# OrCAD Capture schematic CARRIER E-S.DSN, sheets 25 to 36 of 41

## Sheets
25 B1B1: size A4; block Alimentacion/Alimentacion Digital
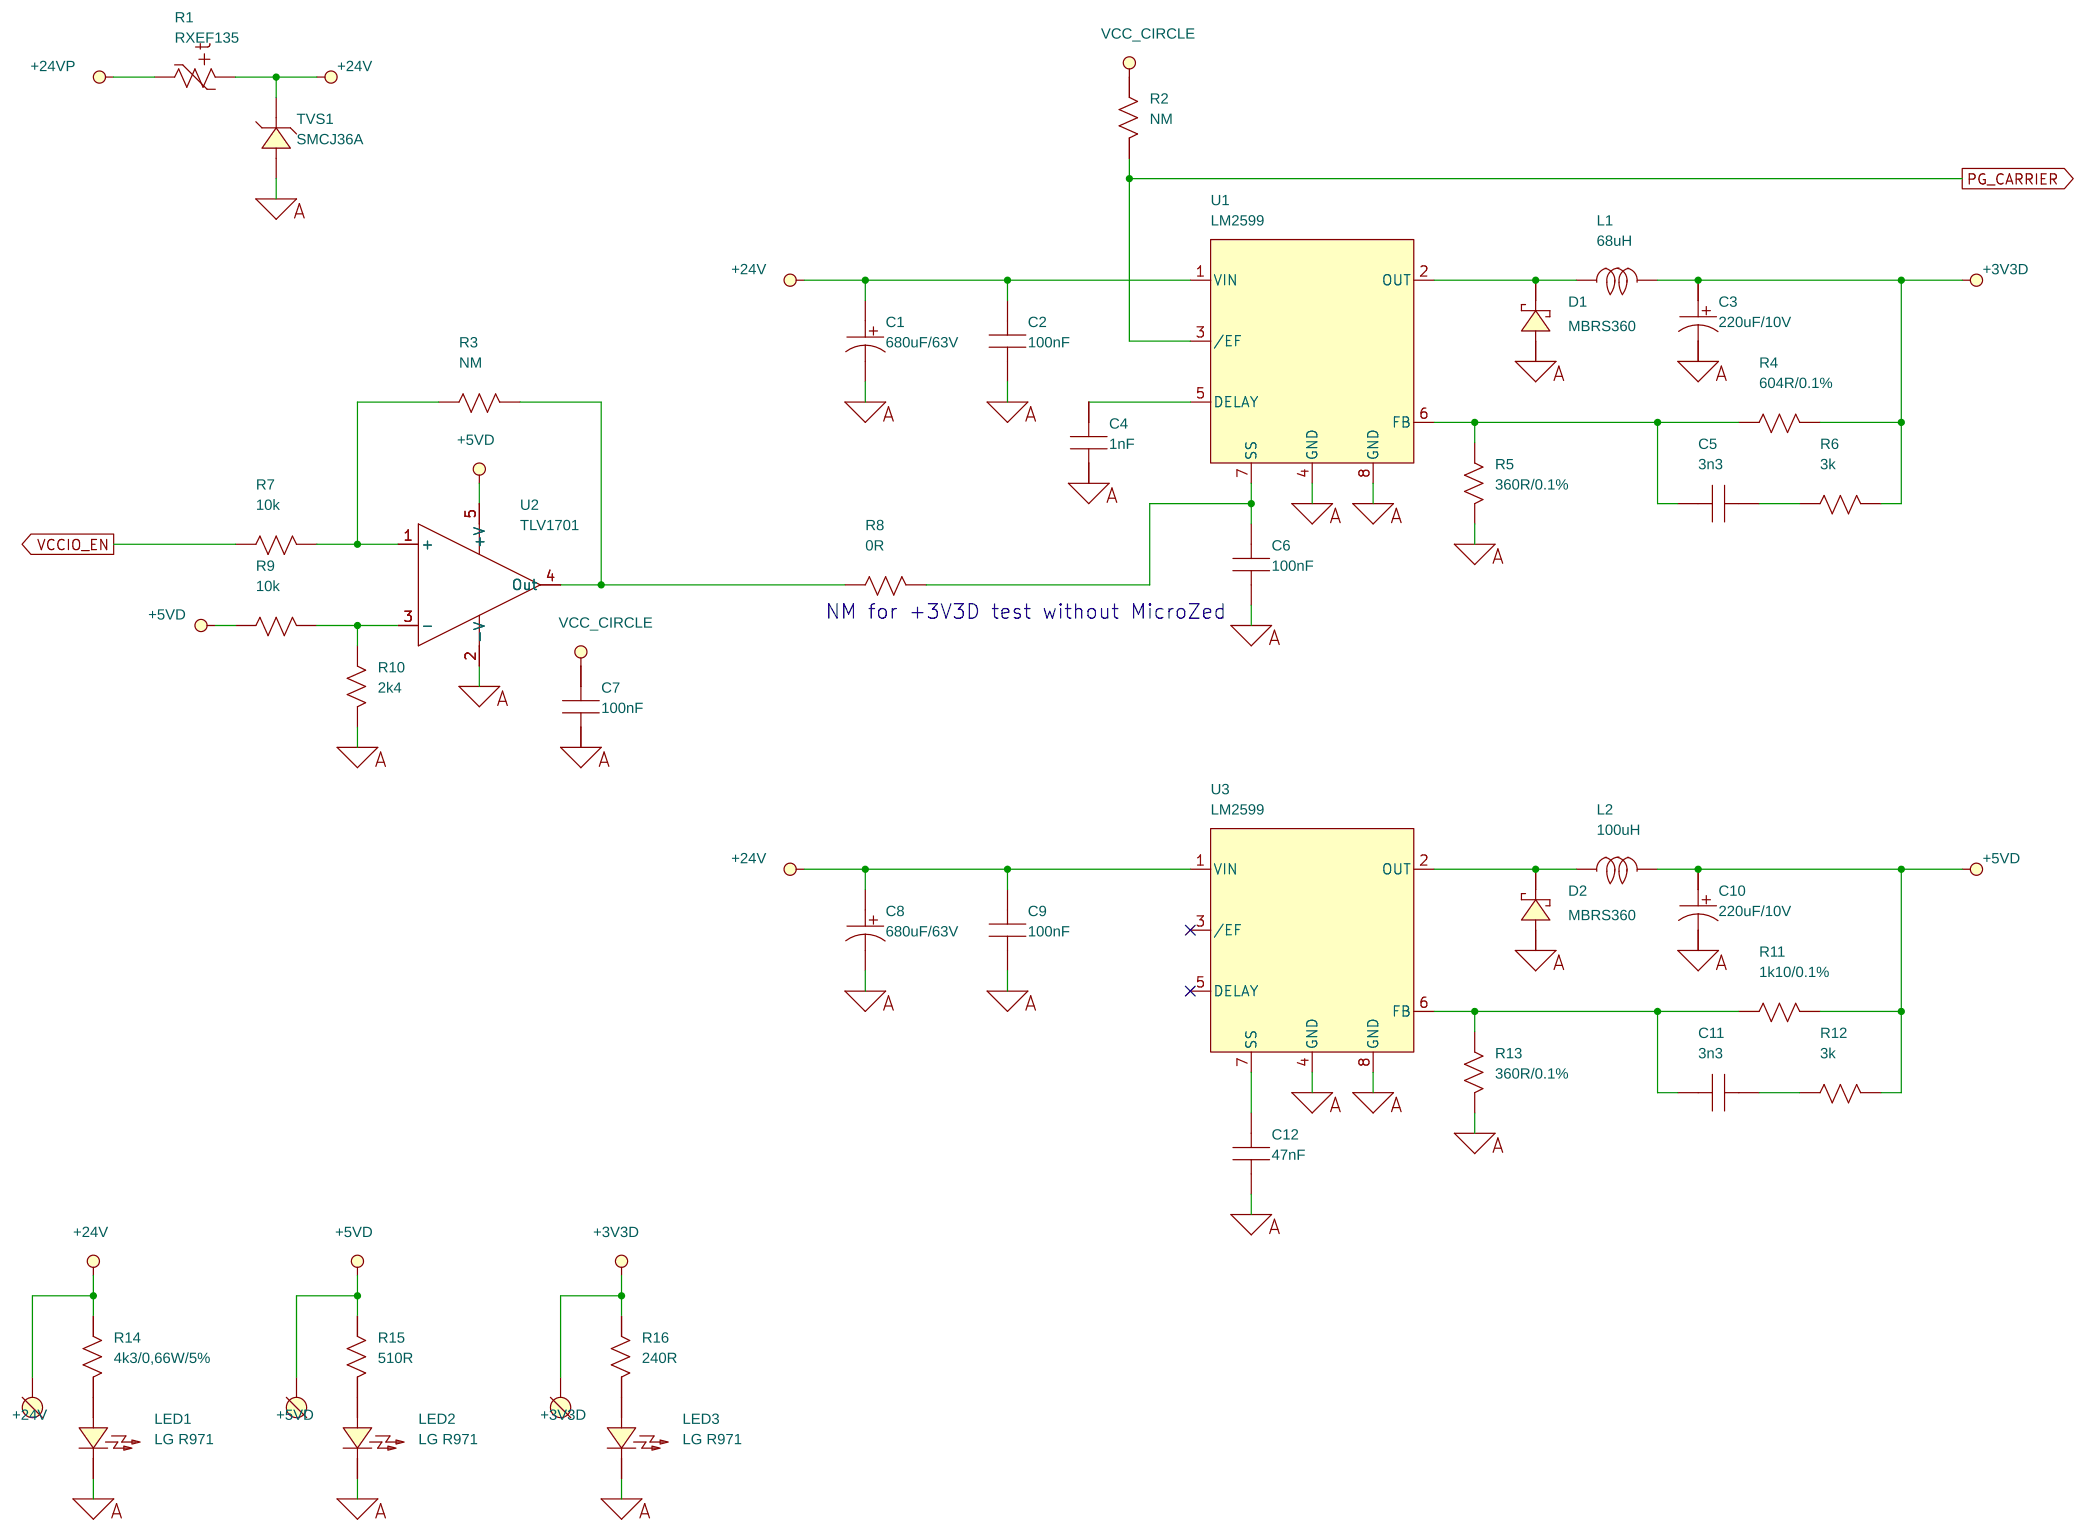
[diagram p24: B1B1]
26 B2: size A4; block IF MicroZed
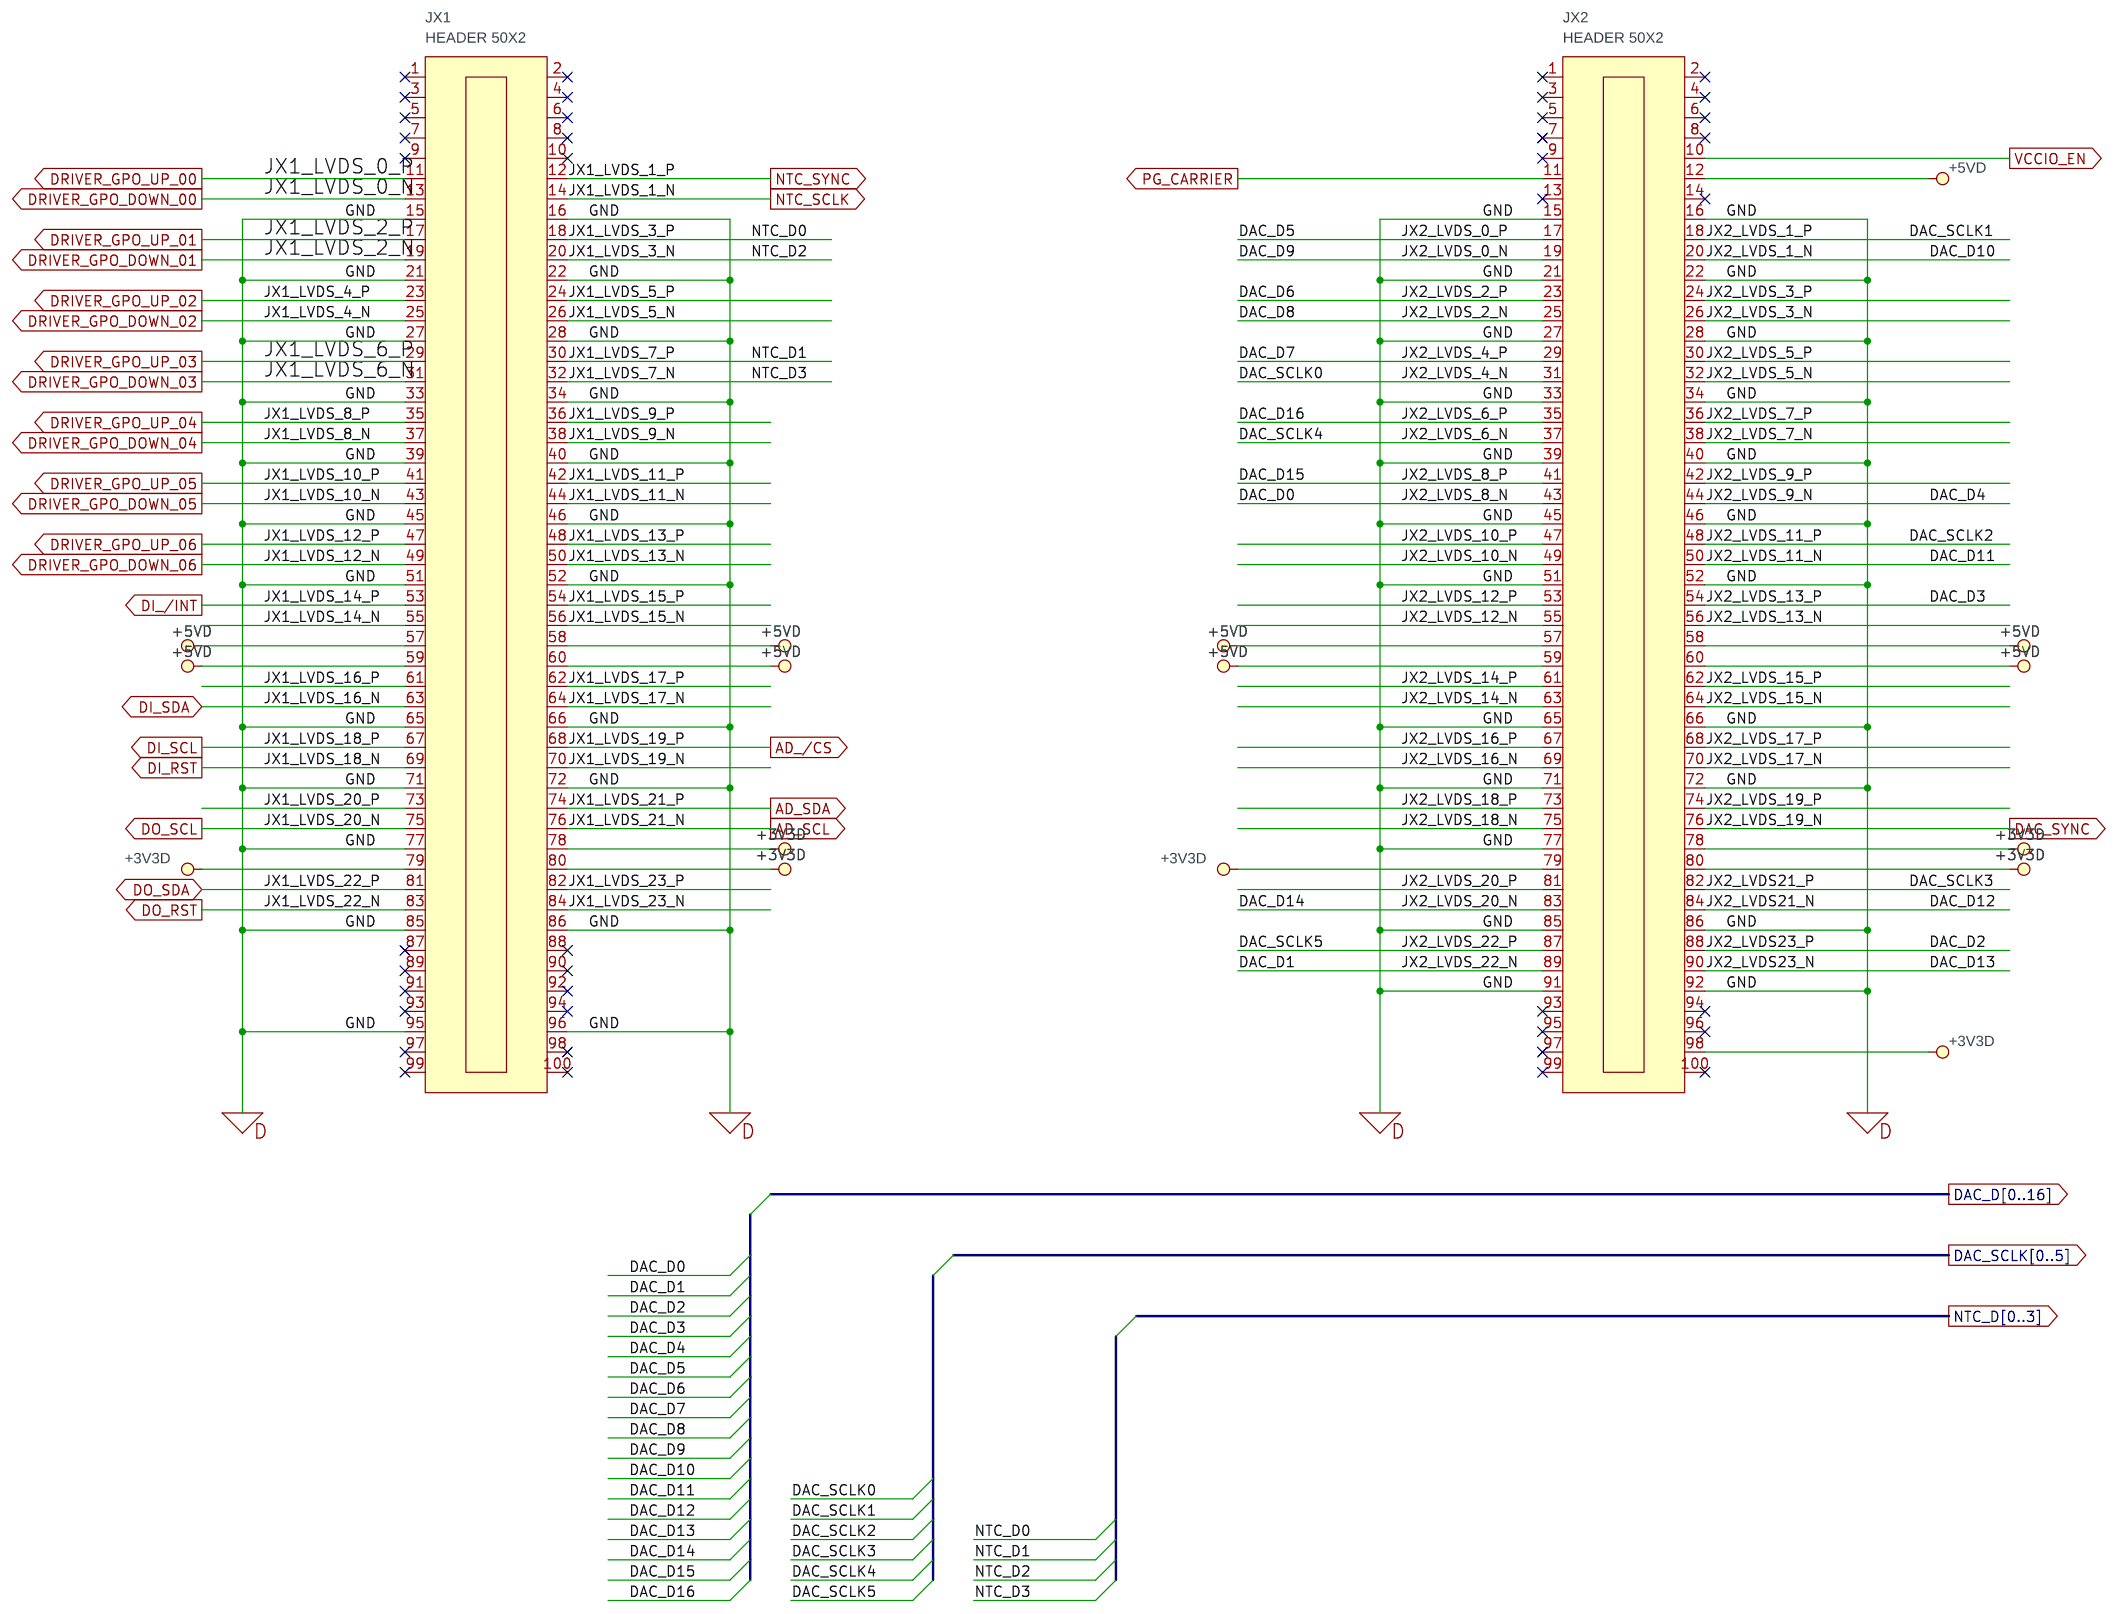
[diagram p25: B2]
27 B3B3
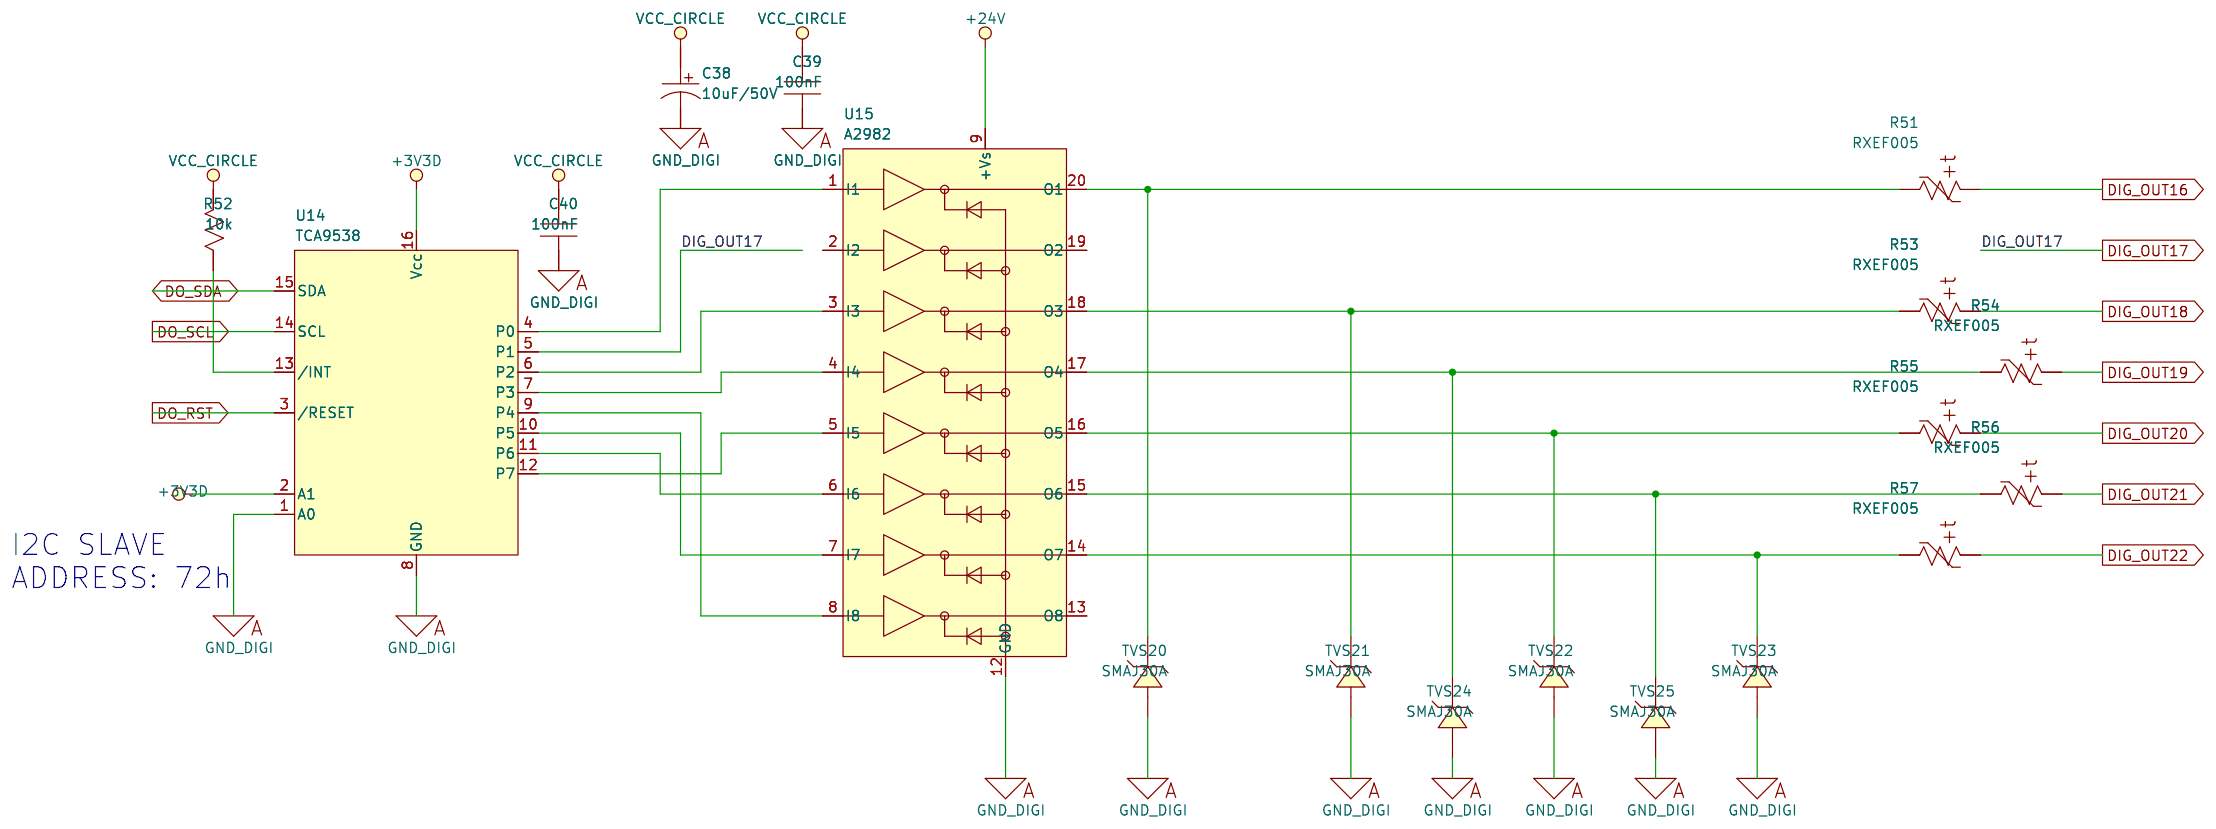
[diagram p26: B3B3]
28 B3B1
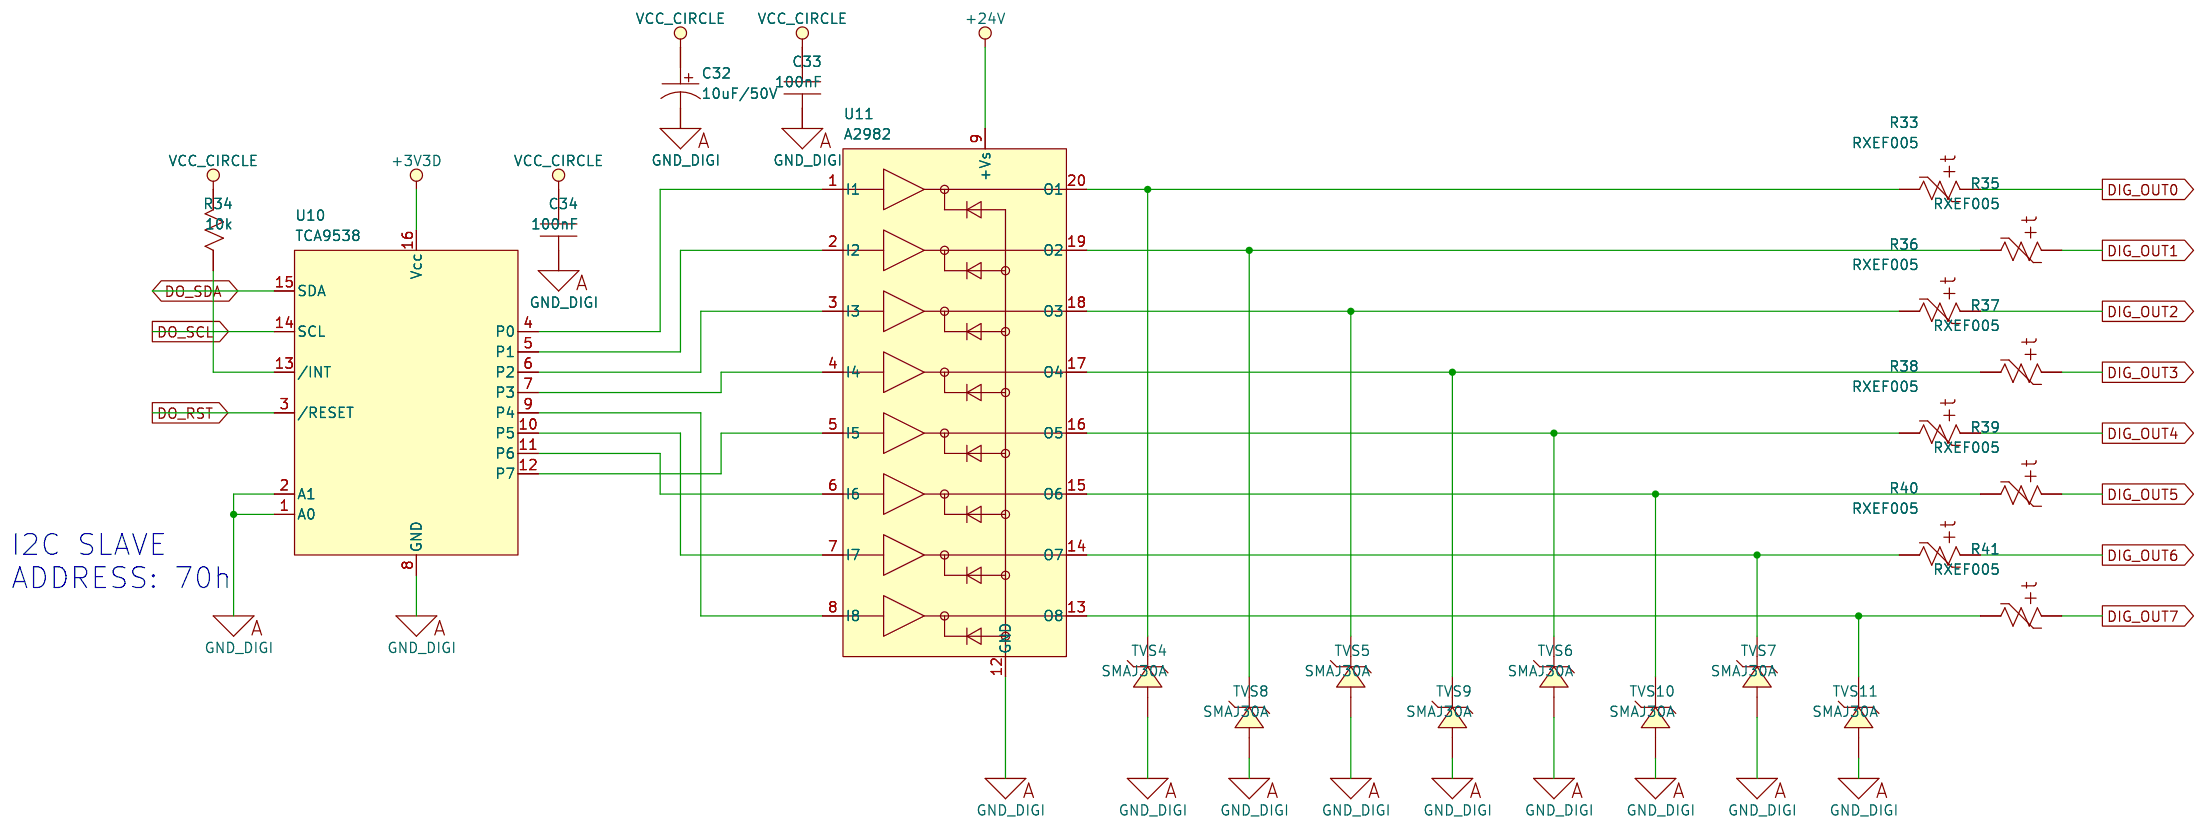
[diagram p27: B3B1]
29 B3B4
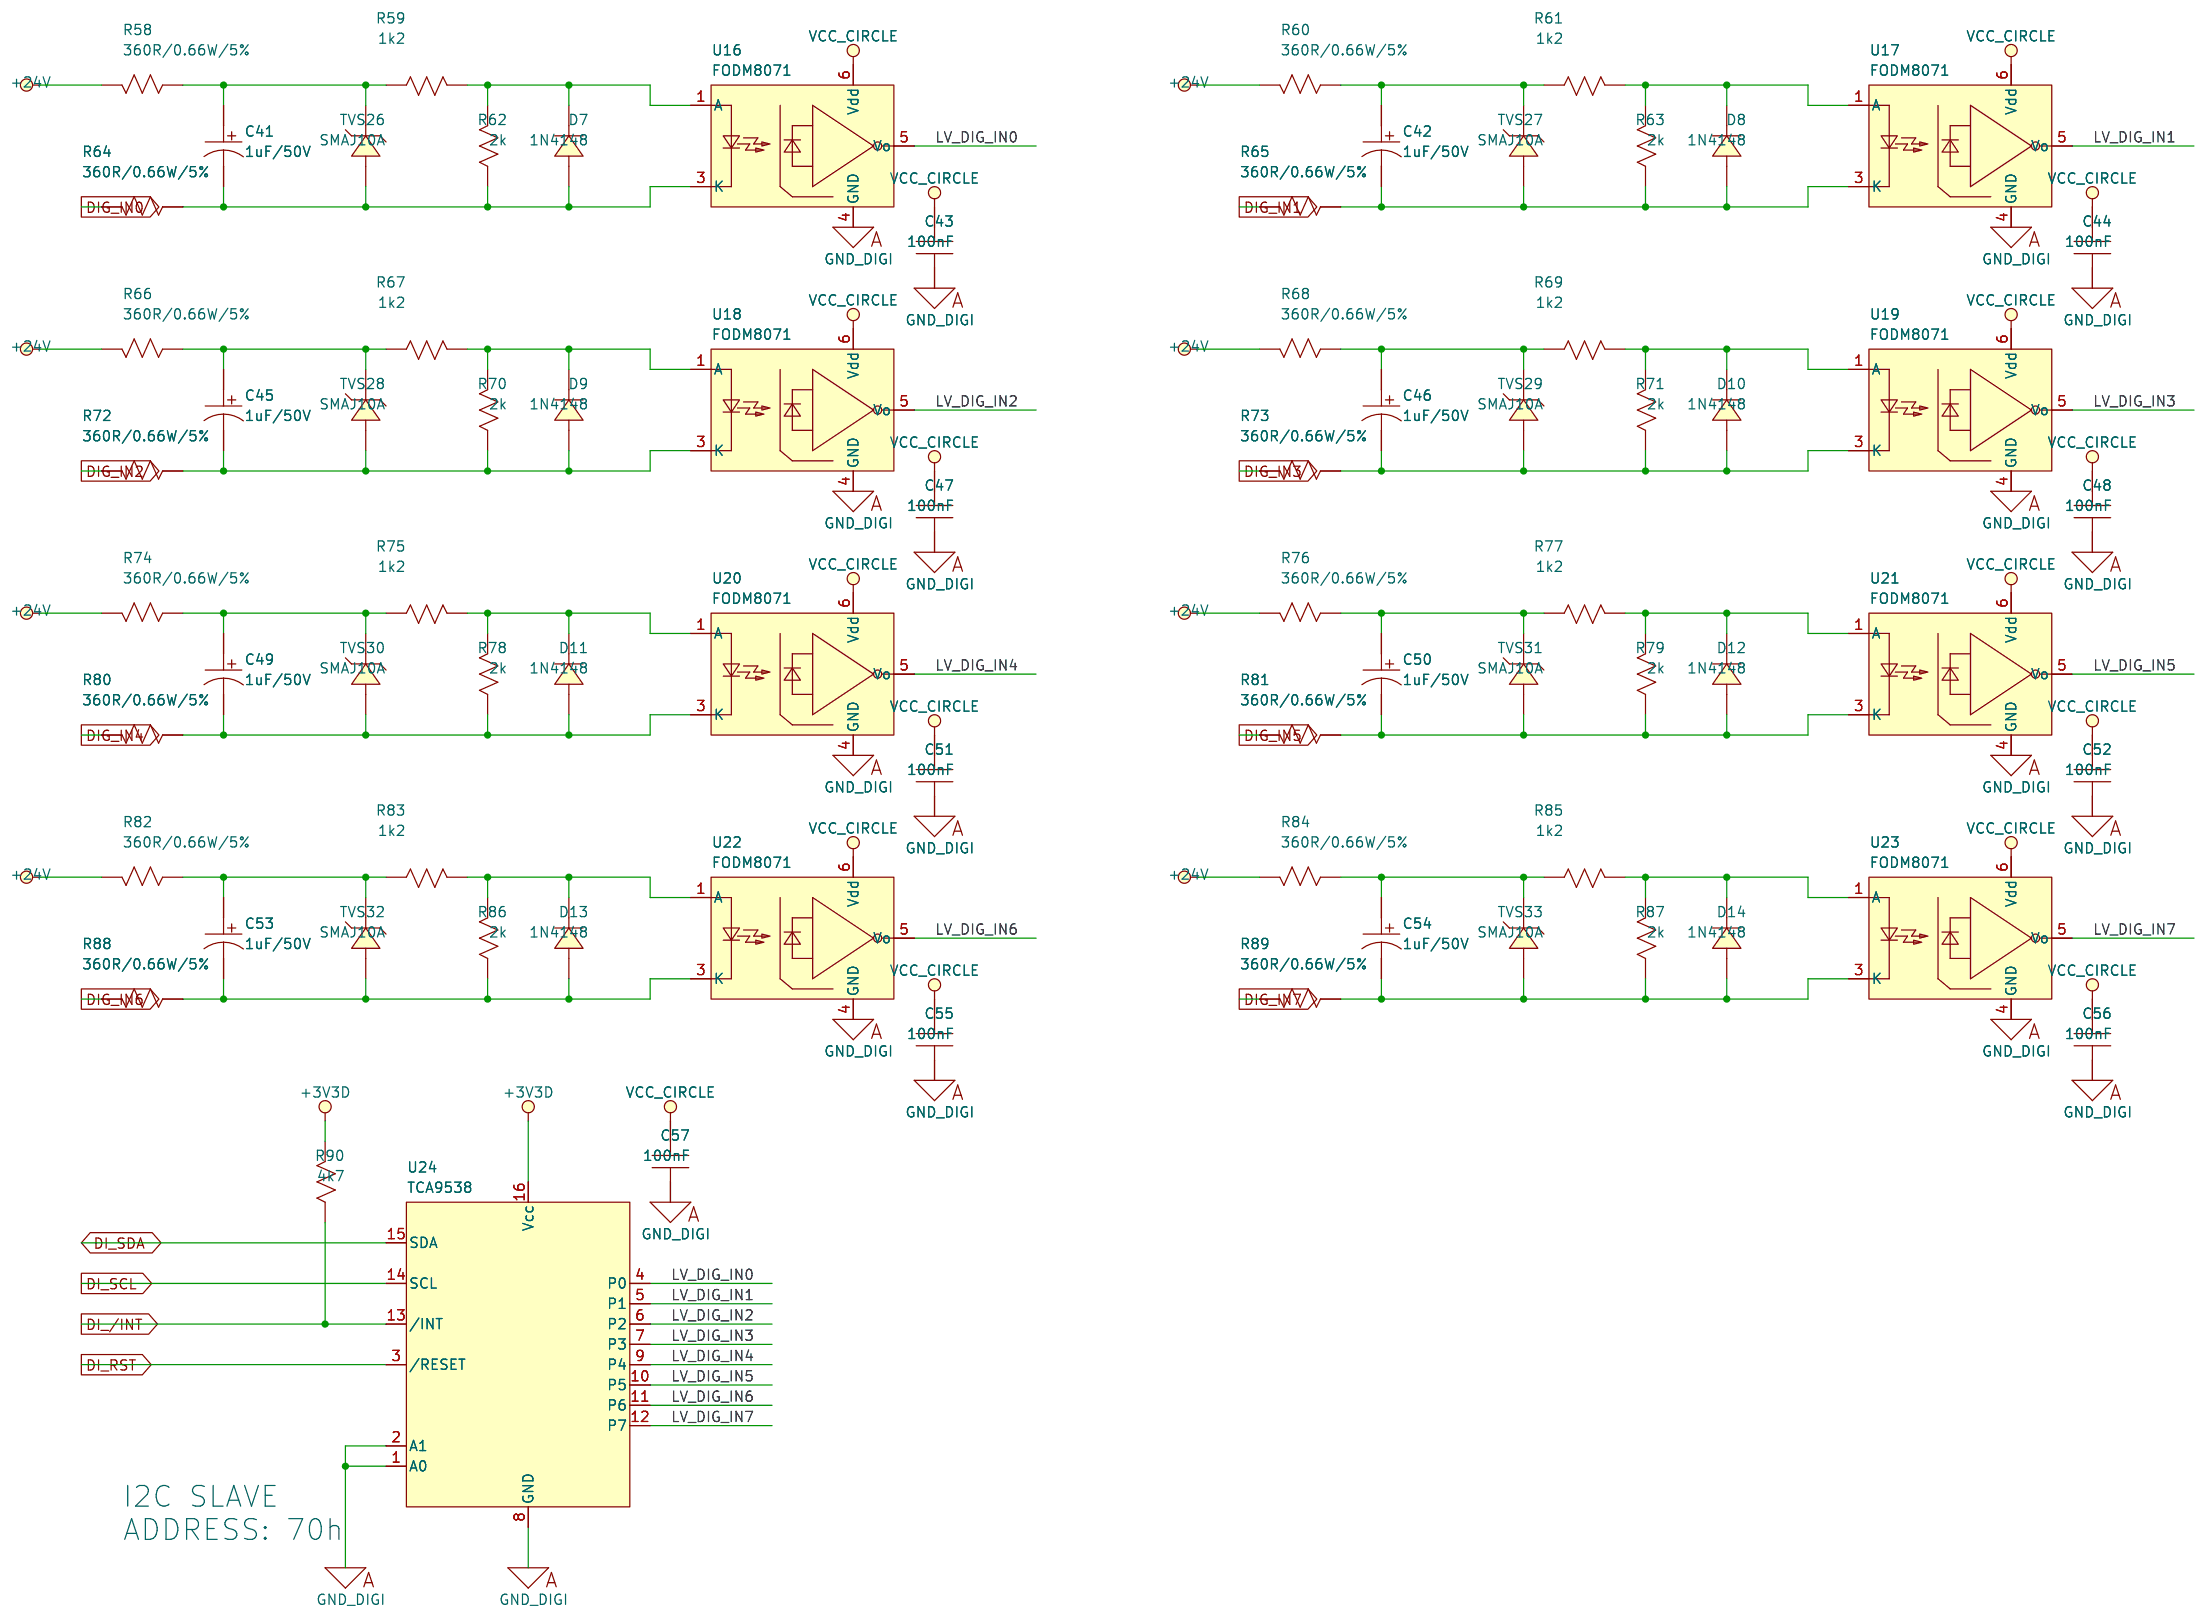
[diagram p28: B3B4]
30 B3B2
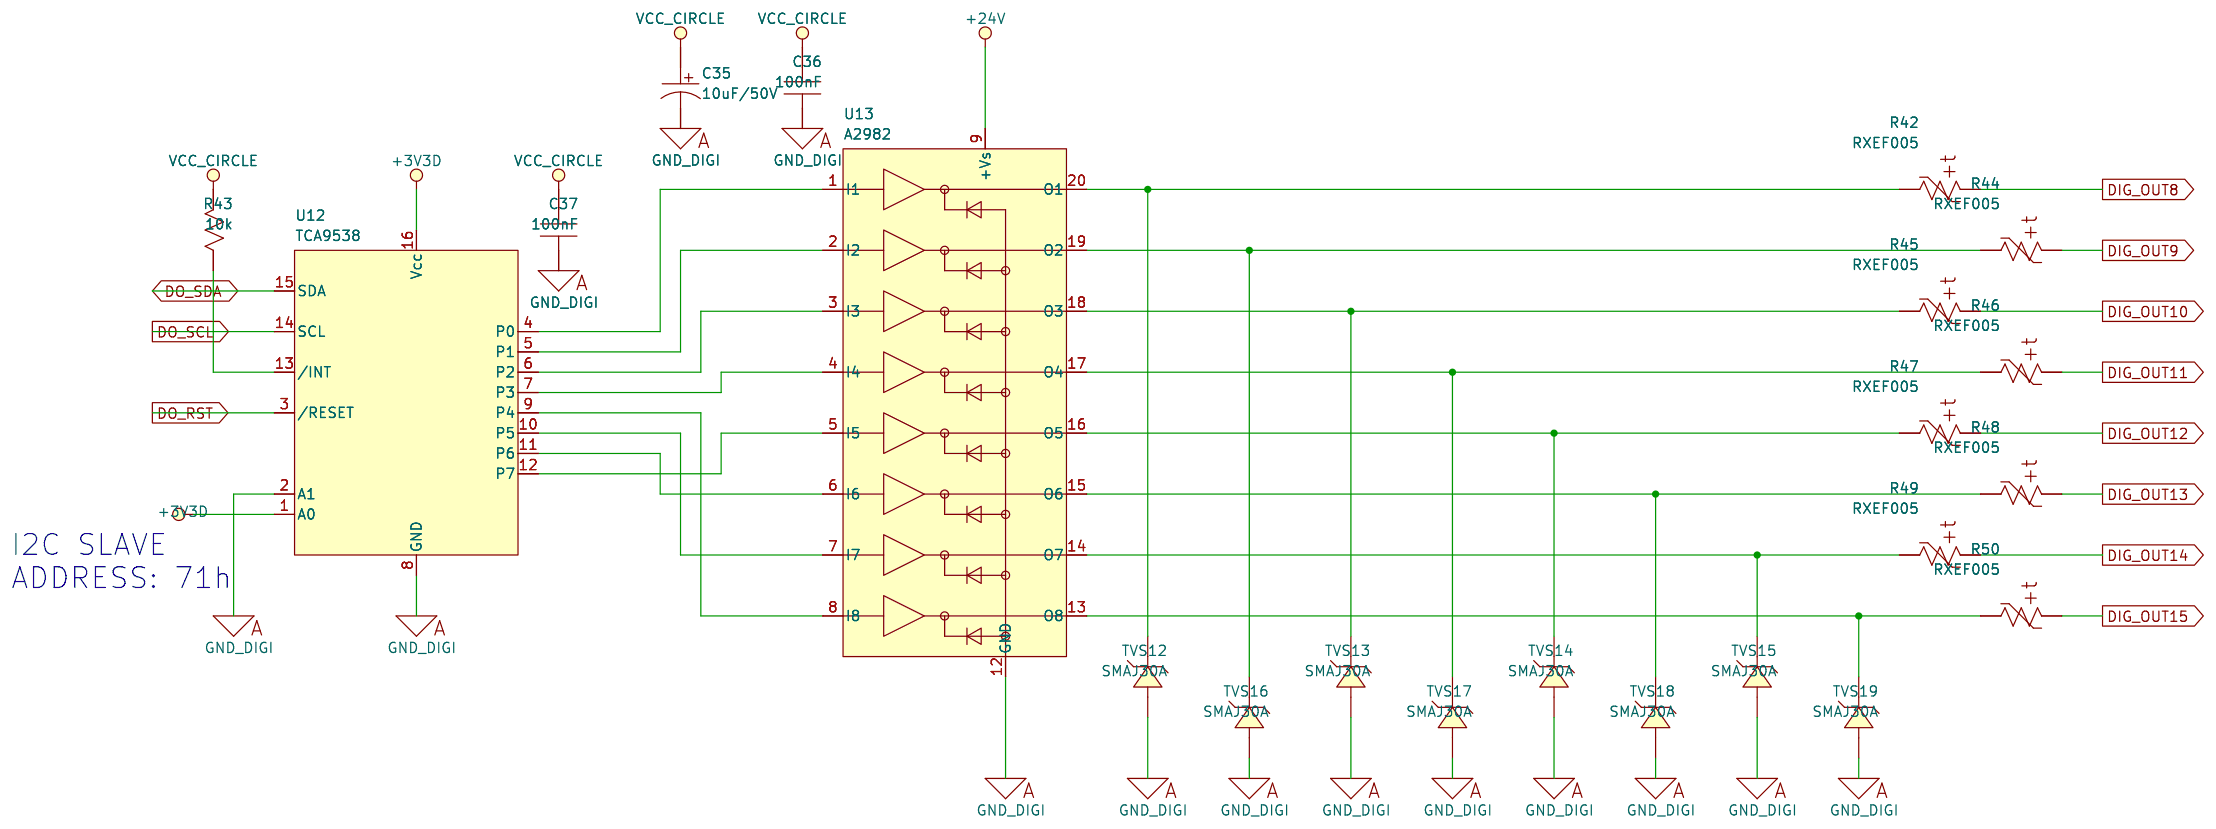
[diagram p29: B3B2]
31 B5: size A4; block Drivers IGBT
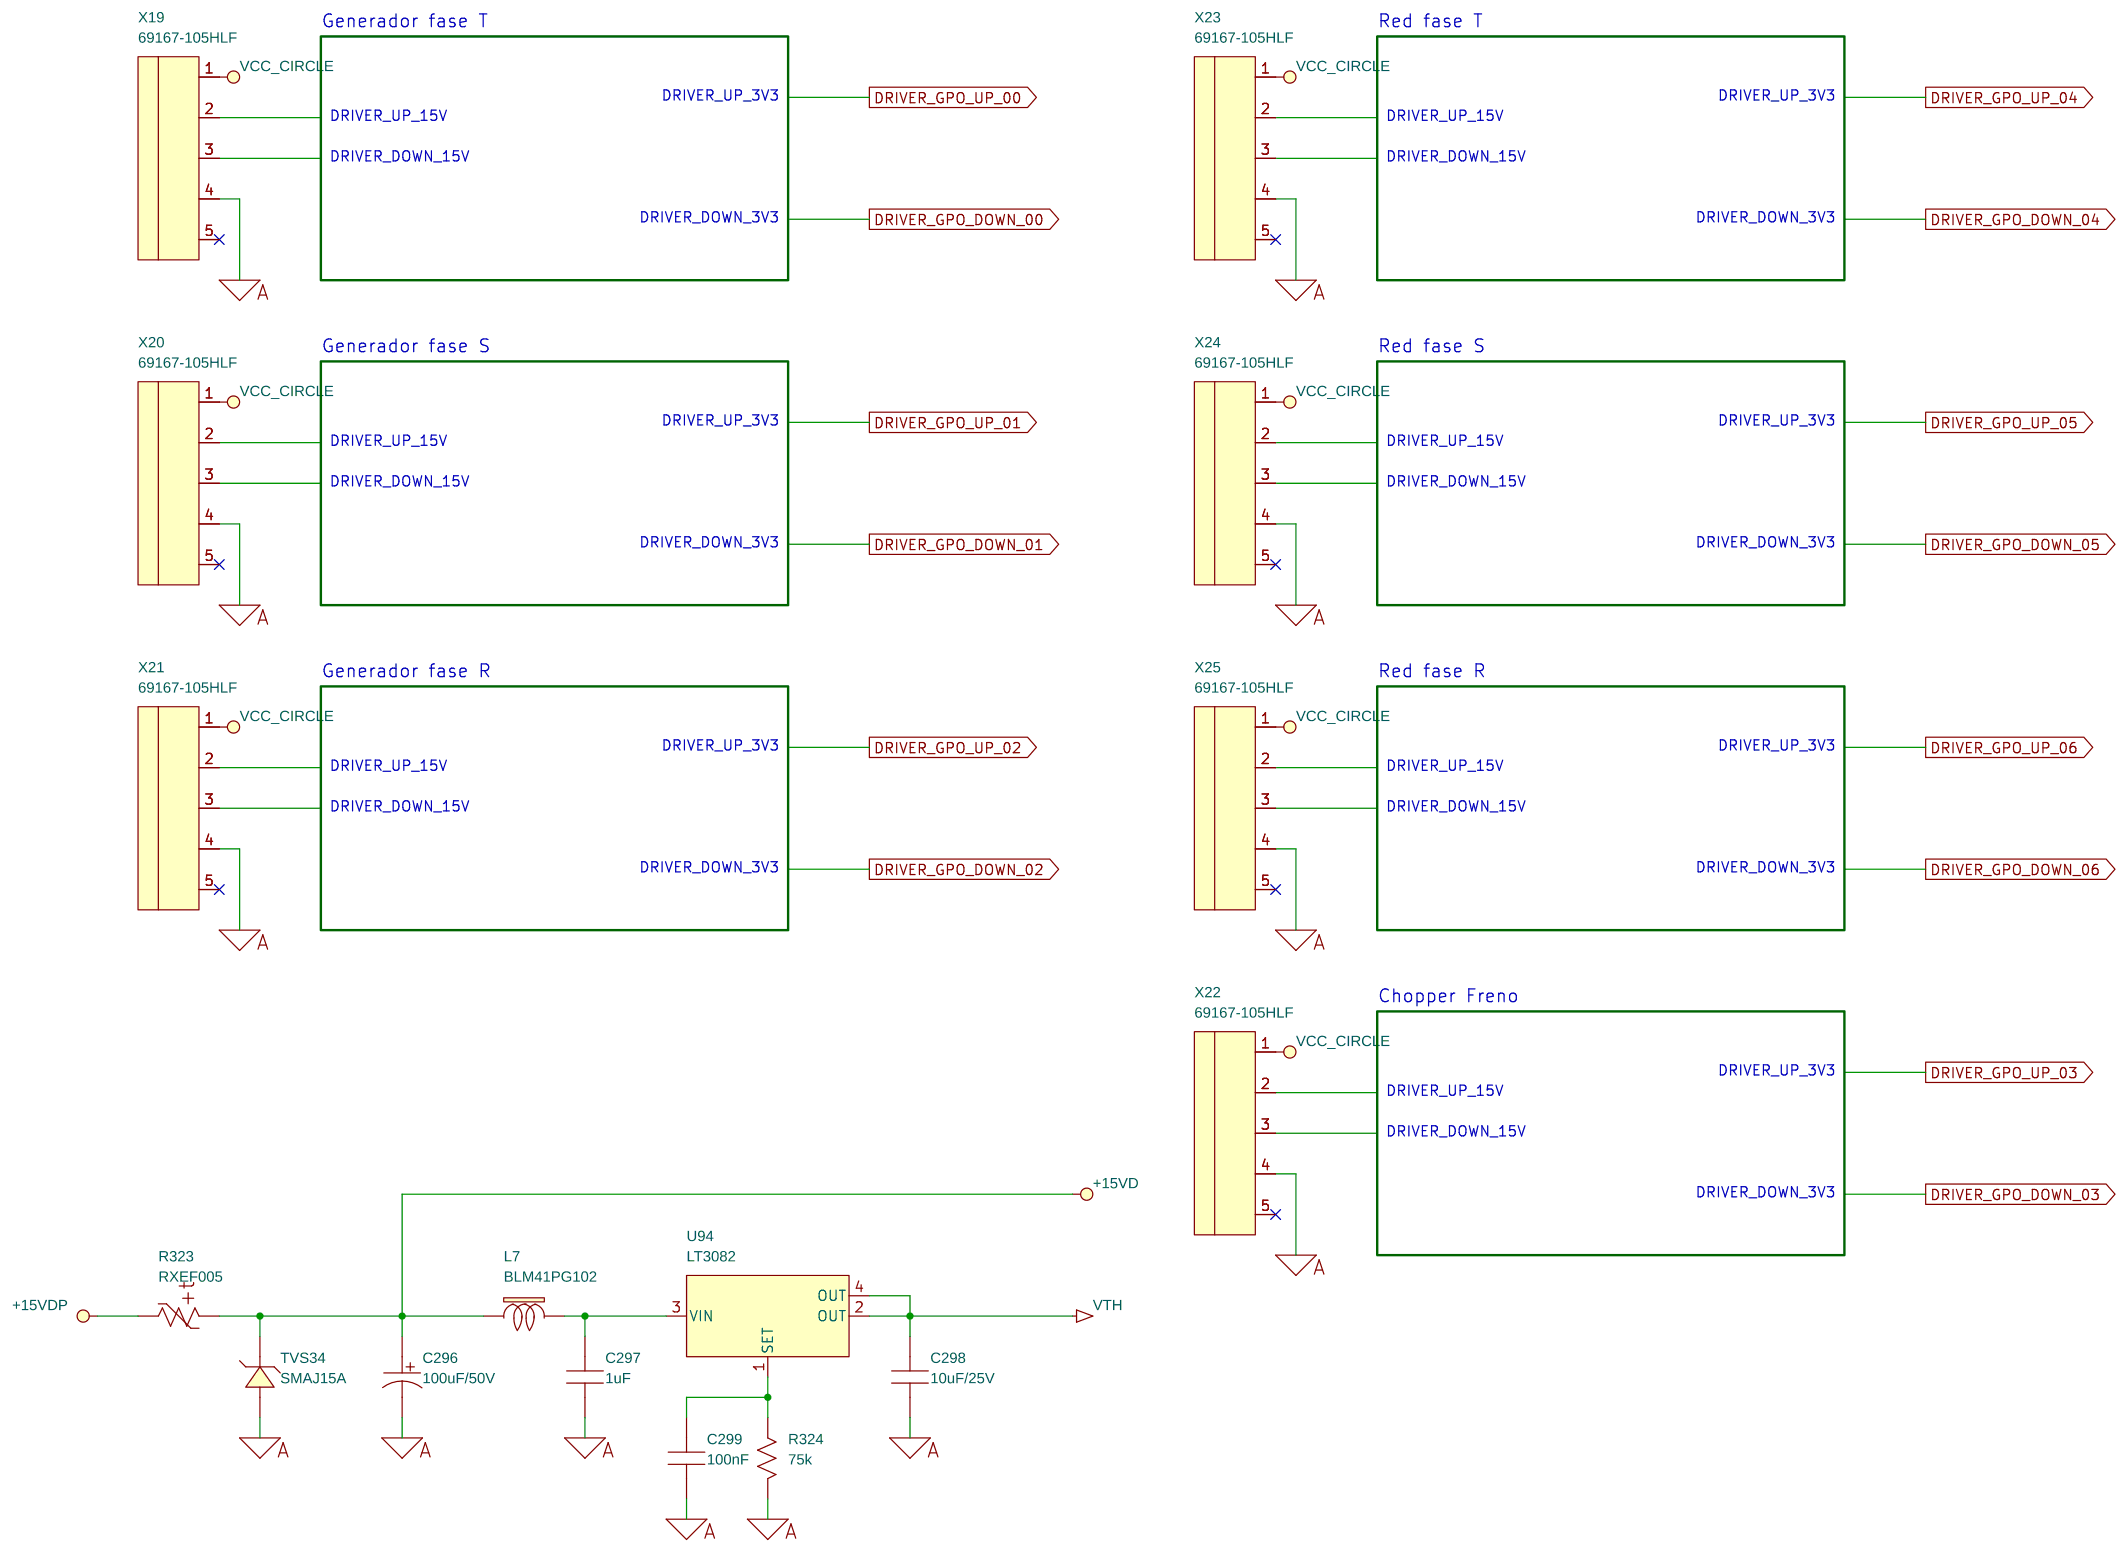
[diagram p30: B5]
32 B5B5: size A4; block Drivers IGBT/Red fase T
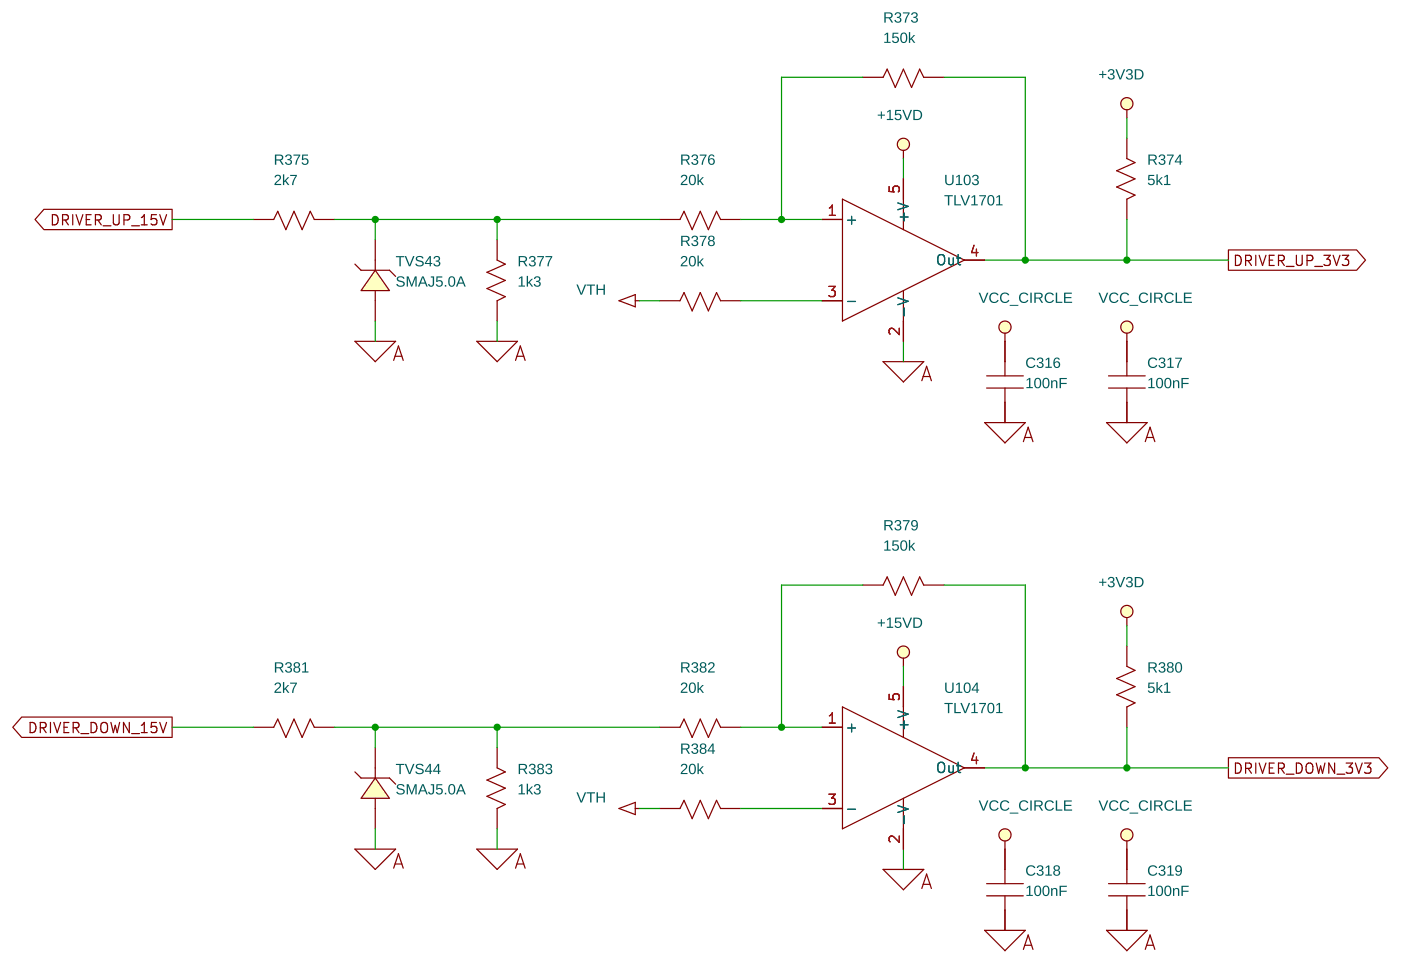
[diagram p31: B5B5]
33 B5B2: size A4; block Drivers IGBT/Generador fase S
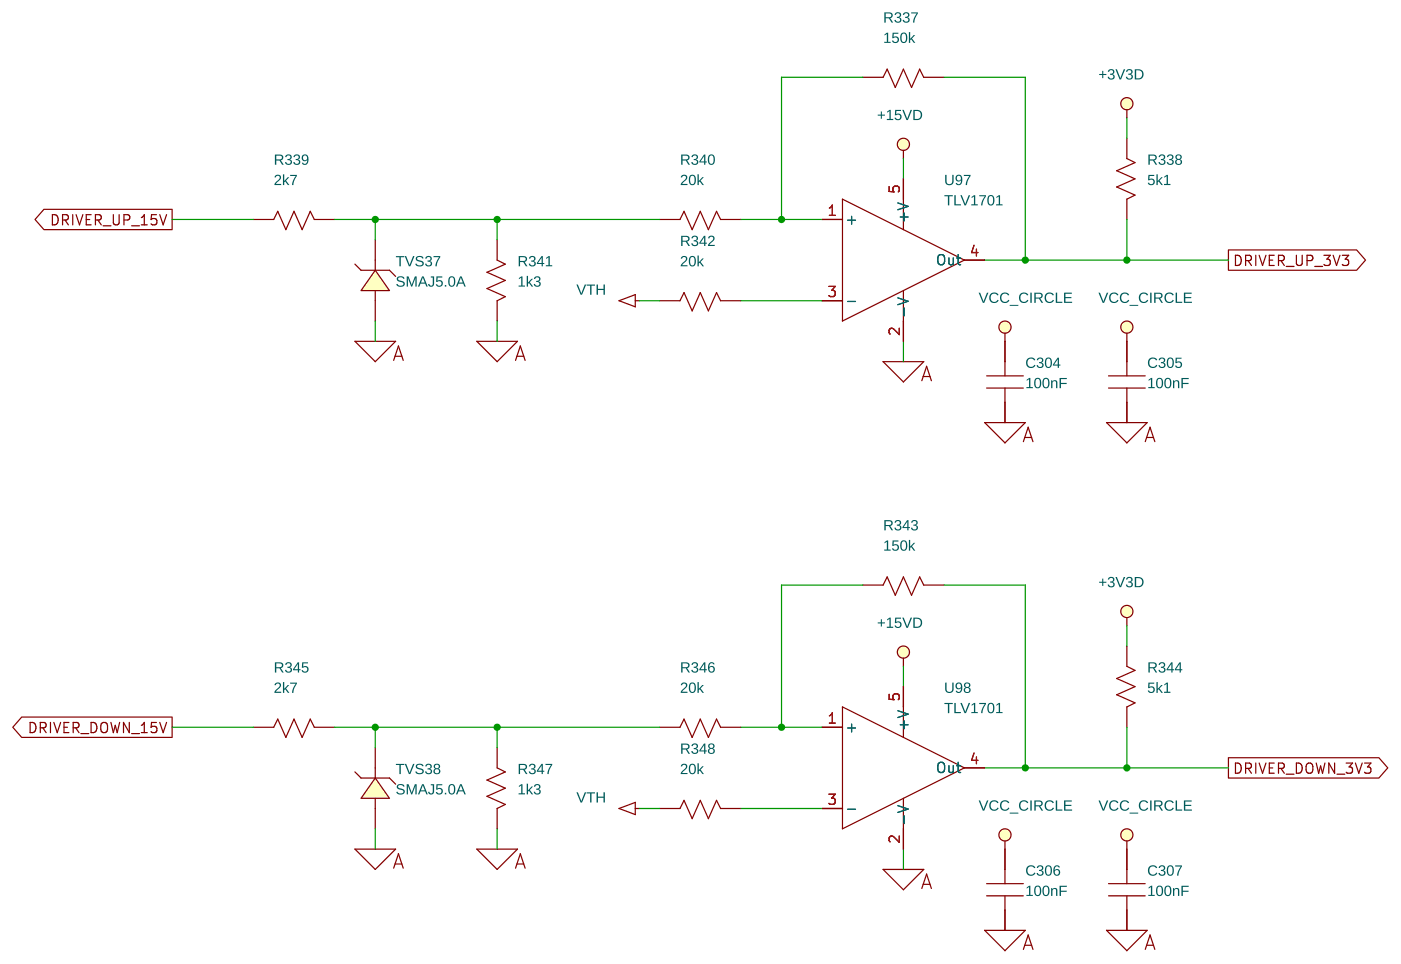
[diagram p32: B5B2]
34 B5B4: size A4; block Drivers IGBT/Chopper Freno
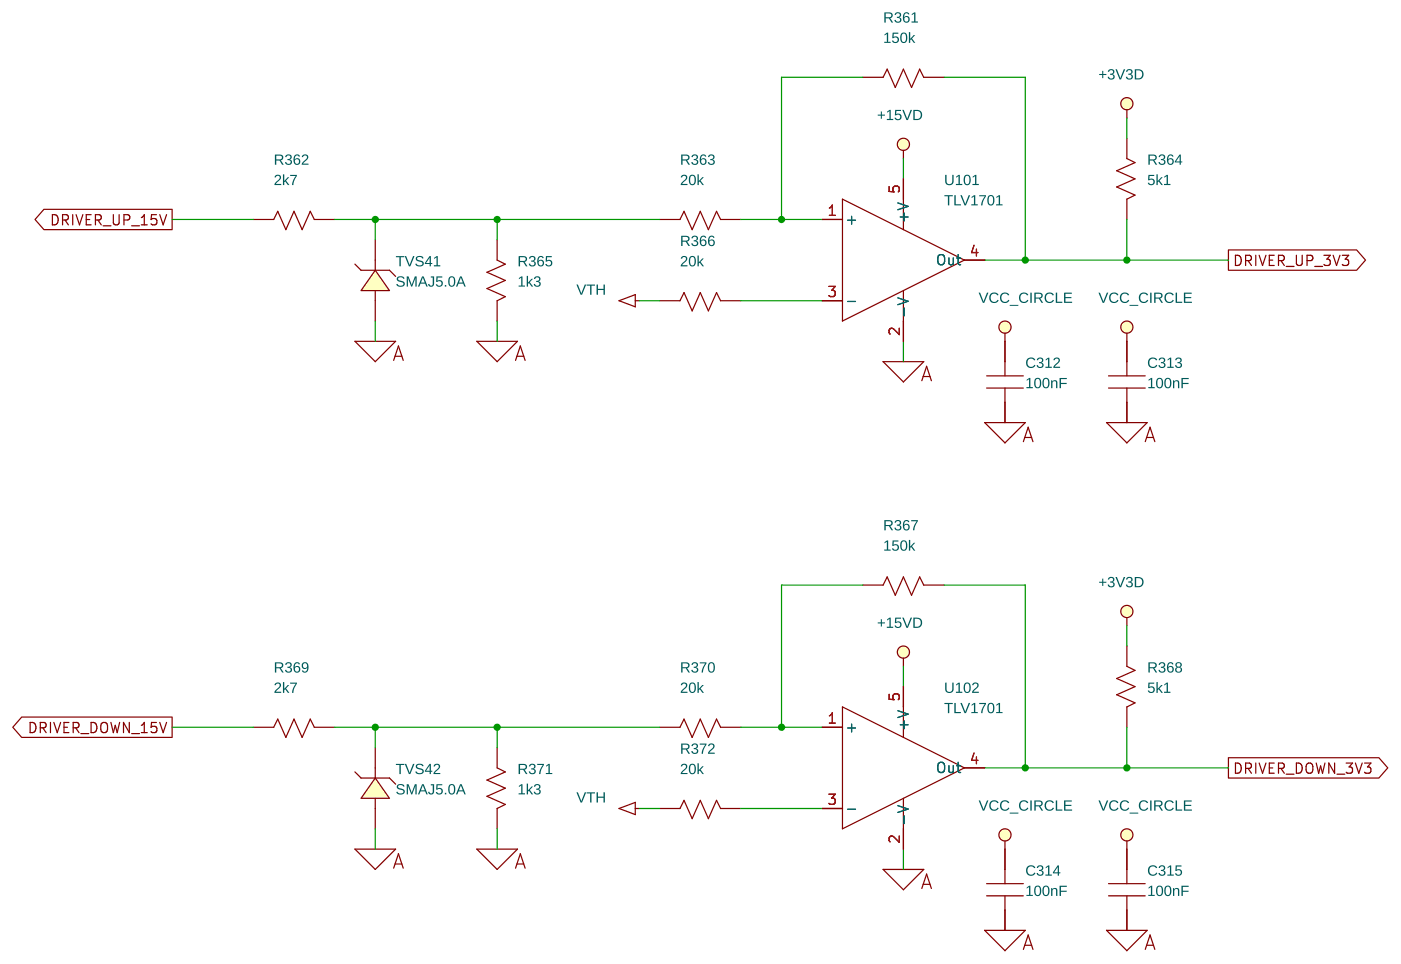
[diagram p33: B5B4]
35 B5B6: size A4; block Drivers IGBT/Red fase S
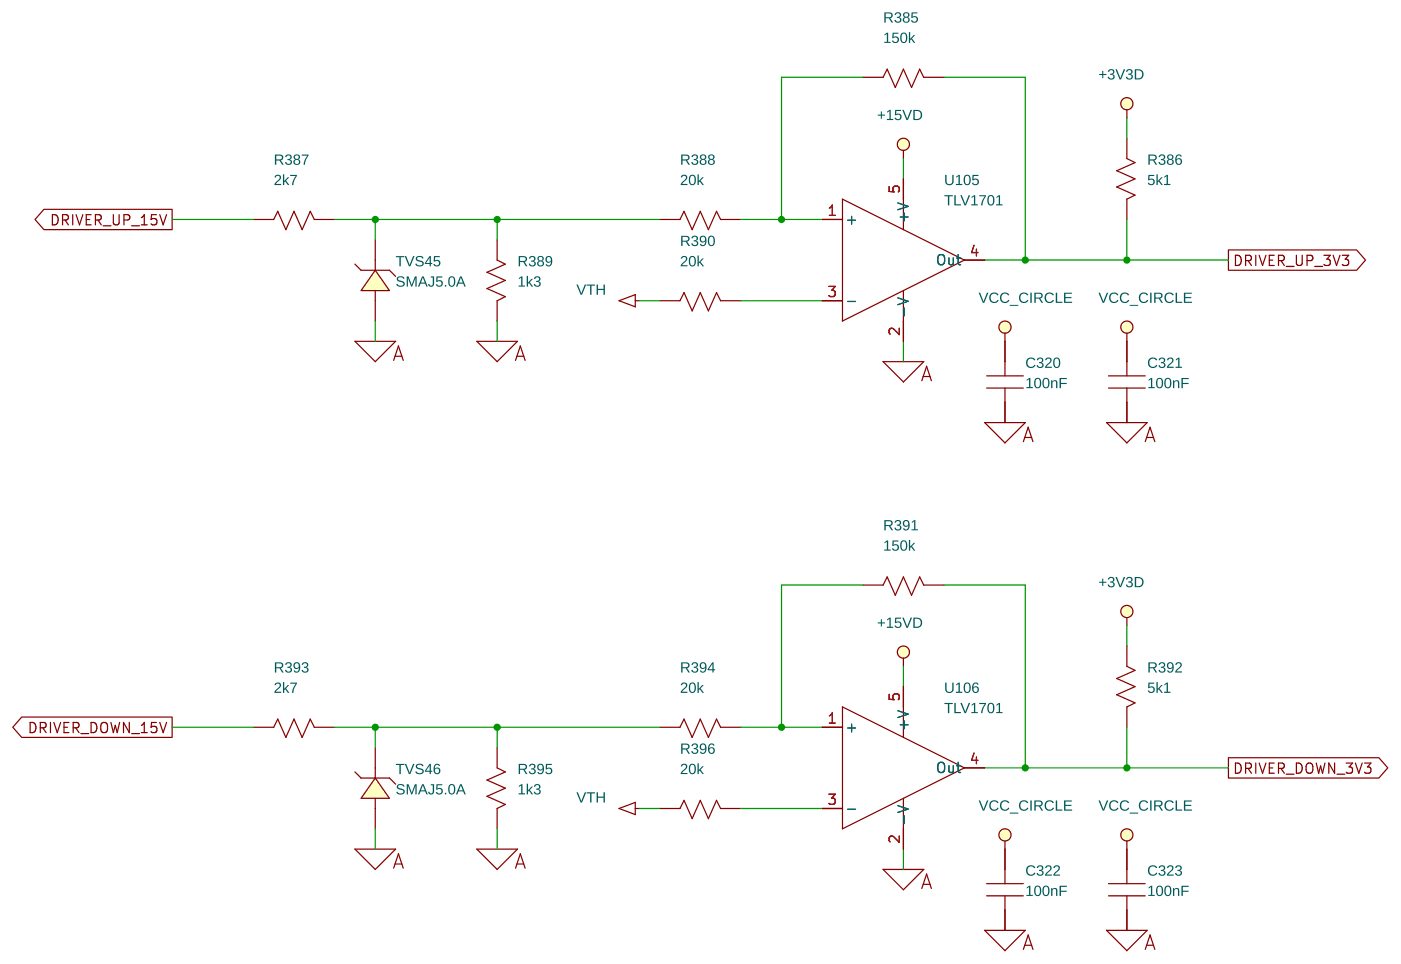
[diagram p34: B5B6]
36 B5B1: size A4; block Drivers IGBT/Generador fase T
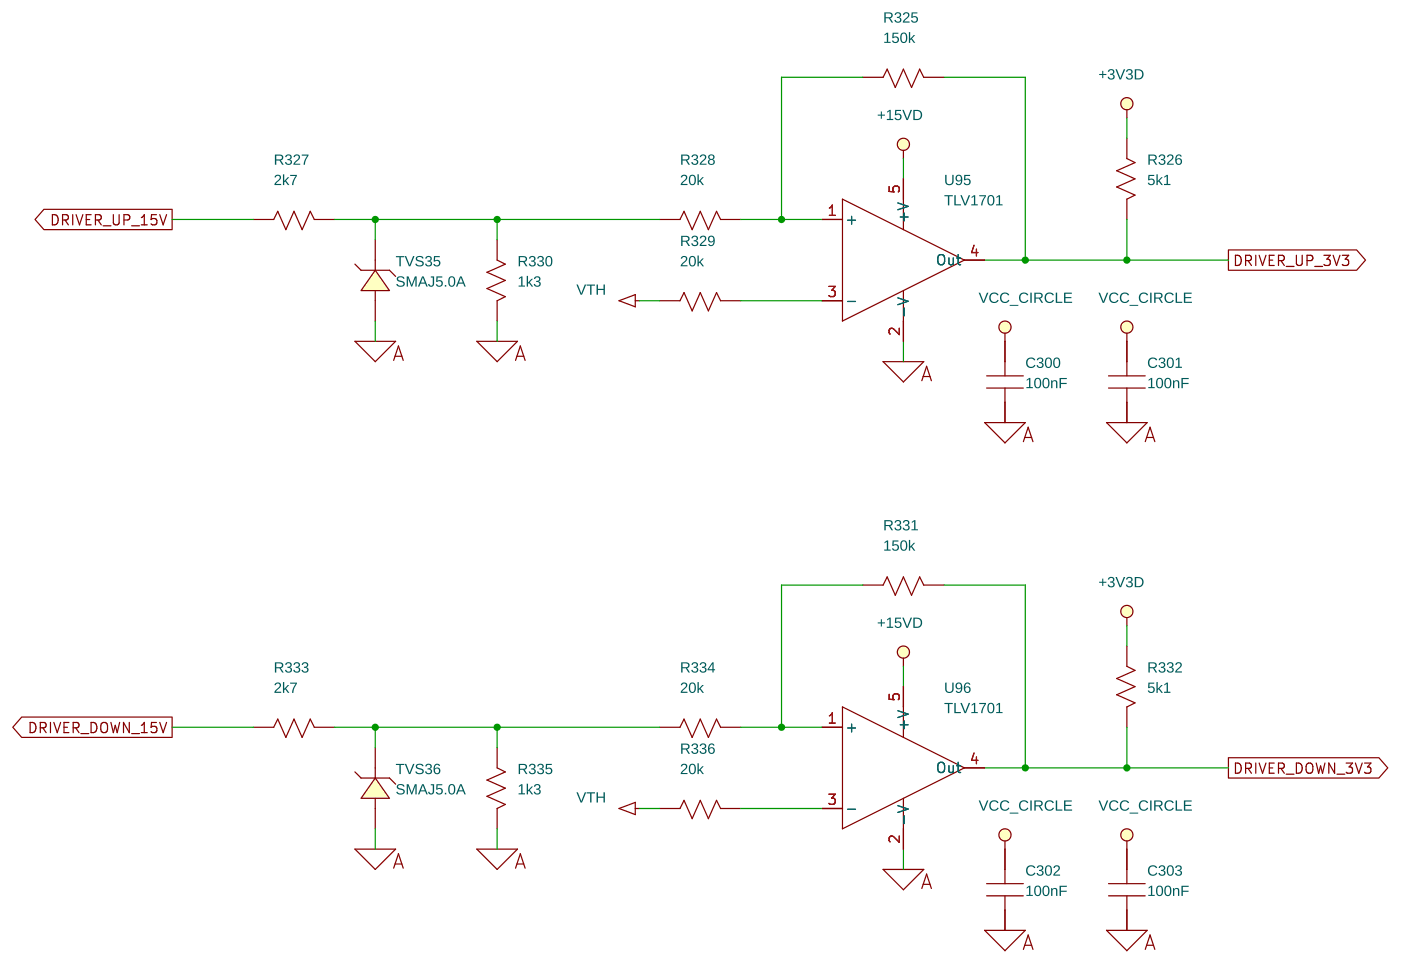
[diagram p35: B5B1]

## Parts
sheet B1B1
+3V3D  TEST POINT  [TP/.040/.76]
+5VD  TEST POINT  [TP/.040/.76]
+24V  TEST POINT  [TP/.040/.76]
C1  680uF/63V  [CYL/D.730/LS.300/.100/.044/IPC-7351 (2005)/NORMAL]
C2  100nF  [C/SM/0805/IPC-7351 (2005)/NORMAL]
C3  220uF/10V  [SM/D-2916/IPC-7351 (2005)/NORMAL]
C4  1nF  [C/SM/0805/IPC-7351 (2005)/NORMAL]
C5  3n3  [C/SM/0805/IPC-7351 (2005)/NORMAL]
C6  100nF  [C/SM/0805/IPC-7351 (2005)/NORMAL]
C7  100nF  [C/SM/0805/IPC-7351 (2005)/NORMAL]
C8  680uF/63V  [CYL/D.730/LS.300/.100/.044/IPC-7351 (2005)/NORMAL]
C9  100nF  [C/SM/0805/IPC-7351 (2005)/NORMAL]
C10  220uF/10V  [SM/D-2916/IPC-7351 (2005)/NORMAL]
C11  3n3  [C/SM/0805/IPC-7351 (2005)/NORMAL]
C12  47nF  [C/SM/0805/IPC-7351 (2005)/NORMAL]
D1  MBRS360  [SM/DO214AA/IPC-7351 (2005)/NORMAL]
D2  MBRS360  [SM/DO214AA/IPC-7351 (2005)/NORMAL]
L1  68uH  [L/SM/12X12MM/IPC-7351 (2005)/NORMAL]
L2  100uH  [L/SM/12X12MM/IPC-7351 (2005)/NORMAL]
LED1  LG R971  [LED/SM/0805/IPC-7351 (2005)/NORMAL]
LED2  LG R971  [LED/SM/0805/IPC-7351 (2005)/NORMAL]
LED3  LG R971  [LED/SM/0805/IPC-7351 (2005)/NORMAL]
R1  RXEF135  [DISC/.200X.080/LS.550X.150/.076/.040/IPC-7351 (2005)/NORMAL]
R2  NM  [R/SM/0805/IPC-7351 (2005)/NORMAL]
R3  NM  [R/SM/0805/IPC-7351 (2005)/NORMAL]
R4  604R/0.1%  [R/SM/0805/IPC-7351 (2005)/NORMAL]
R5  360R/0.1%  [R/SM/0805/IPC-7351 (2005)/NORMAL]
R6  3k  [R/SM/0805/IPC-7351 (2005)/NORMAL]
R7  10k  [R/SM/0805/IPC-7351 (2005)/NORMAL]
R8  0R  [R/SM/0805/IPC-7351 (2005)/NORMAL]
R9  10k  [R/SM/0805/IPC-7351 (2005)/NORMAL]
R10  2k4  [R/SM/0805/IPC-7351 (2005)/NORMAL]
R11  1k10/0.1%  [R/SM/0805/IPC-7351 (2005)/NORMAL]
R12  3k  [R/SM/0805/IPC-7351 (2005)/NORMAL]
R13  360R/0.1%  [R/SM/0805/IPC-7351 (2005)/NORMAL]
R14  4k3/0,66W/5%  [R/SM/1206/IPC-7351 (2005)/NORMAL]
R15  510R  [R/SM/0805/IPC-7351 (2005)/NORMAL]
R16  240R  [R/SM/0805/IPC-7351 (2005)/NORMAL]
TVS1  SMCJ36A  [SM/DO214AB/IPC-7351 (2005)/NORMAL]
U1  LM2599  [SM/TO263/D2PAK/THV 42X.012/7/IPC-7351 (2005)/NORMAL]
U2  TLV1701  [SM/SOT23/5/IPC-7351 (2005)/NORMAL]
U3  LM2599  [SM/TO263/D2PAK/THV 42X.012/7/IPC-7351 (2005)/NORMAL]
sheet B2
JX1  HEADER 50X2  [CONN/SM/AMPHENOL/61083-104400]
JX2  HEADER 50X2  [CONN/SM/AMPHENOL/61083-104400]
sheet B3B1
C32  10uF/50V  [SM/D-2916/IPC-7351 (2005)/NORMAL]
C33  100nF  [C/SM/0805/IPC-7351 (2005)/NORMAL]
C34  100nF  [C/SM/0805/IPC-7351 (2005)/NORMAL]
R33  RXEF005  [DISC/.200X.050/LS.320X.150/.064/.030/IPC-7351 (2005)/NORMAL]
R34  10k  [R/SM/0805/IPC-7351 (2005)/NORMAL]
R35  RXEF005  [DISC/.200X.050/LS.320X.150/.064/.030/IPC-7351 (2005)/NORMAL]
R36  RXEF005  [DISC/.200X.050/LS.320X.150/.064/.030/IPC-7351 (2005)/NORMAL]
R37  RXEF005  [DISC/.200X.050/LS.320X.150/.064/.030/IPC-7351 (2005)/NORMAL]
R38  RXEF005  [DISC/.200X.050/LS.320X.150/.064/.030/IPC-7351 (2005)/NORMAL]
R39  RXEF005  [DISC/.200X.050/LS.320X.150/.064/.030/IPC-7351 (2005)/NORMAL]
R40  RXEF005  [DISC/.200X.050/LS.320X.150/.064/.030/IPC-7351 (2005)/NORMAL]
R41  RXEF005  [DISC/.200X.050/LS.320X.150/.064/.030/IPC-7351 (2005)/NORMAL]
TVS4  SMAJ30A  [SM/DO214AC/IPC-7351 (2005)/NORMAL]
TVS5  SMAJ30A  [SM/DO214AC/IPC-7351 (2005)/NORMAL]
TVS6  SMAJ30A  [SM/DO214AC/IPC-7351 (2005)/NORMAL]
TVS7  SMAJ30A  [SM/DO214AC/IPC-7351 (2005)/NORMAL]
TVS8  SMAJ30A  [SM/DO214AC/IPC-7351 (2005)/NORMAL]
TVS9  SMAJ30A  [SM/DO214AC/IPC-7351 (2005)/NORMAL]
TVS10  SMAJ30A  [SM/DO214AC/IPC-7351 (2005)/NORMAL]
TVS11  SMAJ30A  [SM/DO214AC/IPC-7351 (2005)/NORMAL]
U10  TCA9538  [SM/TSSOP/.0255/16/WB.220/L.210/IPC-7351 (2005)/NORMAL]
U11  A2982  [SM/SOIC.050/20/WB.300/L.510/IPC-7351 (2005)/NORMAL]
sheet B3B2
C35  10uF/50V  [SM/D-2916/IPC-7351 (2005)/NORMAL]
C36  100nF  [C/SM/0805/IPC-7351 (2005)/NORMAL]
C37  100nF  [C/SM/0805/IPC-7351 (2005)/NORMAL]
R42  RXEF005  [DISC/.200X.050/LS.320X.150/.064/.030/IPC-7351 (2005)/NORMAL]
R43  10k  [R/SM/0805/IPC-7351 (2005)/NORMAL]
R44  RXEF005  [DISC/.200X.050/LS.320X.150/.064/.030/IPC-7351 (2005)/NORMAL]
R45  RXEF005  [DISC/.200X.050/LS.320X.150/.064/.030/IPC-7351 (2005)/NORMAL]
R46  RXEF005  [DISC/.200X.050/LS.320X.150/.064/.030/IPC-7351 (2005)/NORMAL]
R47  RXEF005  [DISC/.200X.050/LS.320X.150/.064/.030/IPC-7351 (2005)/NORMAL]
R48  RXEF005  [DISC/.200X.050/LS.320X.150/.064/.030/IPC-7351 (2005)/NORMAL]
R49  RXEF005  [DISC/.200X.050/LS.320X.150/.064/.030/IPC-7351 (2005)/NORMAL]
R50  RXEF005  [DISC/.200X.050/LS.320X.150/.064/.030/IPC-7351 (2005)/NORMAL]
TVS12  SMAJ30A  [SM/DO214AC/IPC-7351 (2005)/NORMAL]
TVS13  SMAJ30A  [SM/DO214AC/IPC-7351 (2005)/NORMAL]
TVS14  SMAJ30A  [SM/DO214AC/IPC-7351 (2005)/NORMAL]
TVS15  SMAJ30A  [SM/DO214AC/IPC-7351 (2005)/NORMAL]
TVS16  SMAJ30A  [SM/DO214AC/IPC-7351 (2005)/NORMAL]
TVS17  SMAJ30A  [SM/DO214AC/IPC-7351 (2005)/NORMAL]
TVS18  SMAJ30A  [SM/DO214AC/IPC-7351 (2005)/NORMAL]
TVS19  SMAJ30A  [SM/DO214AC/IPC-7351 (2005)/NORMAL]
U12  TCA9538  [SM/TSSOP/.0255/16/WB.220/L.210/IPC-7351 (2005)/NORMAL]
U13  A2982  [SM/SOIC.050/20/WB.300/L.510/IPC-7351 (2005)/NORMAL]
sheet B3B3
C38  10uF/50V  [SM/D-2916/IPC-7351 (2005)/NORMAL]
C39  100nF  [C/SM/0805/IPC-7351 (2005)/NORMAL]
C40  100nF  [C/SM/0805/IPC-7351 (2005)/NORMAL]
R51  RXEF005  [DISC/.200X.050/LS.320X.150/.064/.030/IPC-7351 (2005)/NORMAL]
R52  10k  [R/SM/0805/IPC-7351 (2005)/NORMAL]
R53  RXEF005  [DISC/.200X.050/LS.320X.150/.064/.030/IPC-7351 (2005)/NORMAL]
R54  RXEF005  [DISC/.200X.050/LS.320X.150/.064/.030/IPC-7351 (2005)/NORMAL]
R55  RXEF005  [DISC/.200X.050/LS.320X.150/.064/.030/IPC-7351 (2005)/NORMAL]
R56  RXEF005  [DISC/.200X.050/LS.320X.150/.064/.030/IPC-7351 (2005)/NORMAL]
R57  RXEF005  [DISC/.200X.050/LS.320X.150/.064/.030/IPC-7351 (2005)/NORMAL]
TVS20  SMAJ30A  [SM/DO214AC/IPC-7351 (2005)/NORMAL]
TVS21  SMAJ30A  [SM/DO214AC/IPC-7351 (2005)/NORMAL]
TVS22  SMAJ30A  [SM/DO214AC/IPC-7351 (2005)/NORMAL]
TVS23  SMAJ30A  [SM/DO214AC/IPC-7351 (2005)/NORMAL]
TVS24  SMAJ30A  [SM/DO214AC/IPC-7351 (2005)/NORMAL]
TVS25  SMAJ30A  [SM/DO214AC/IPC-7351 (2005)/NORMAL]
U14  TCA9538  [SM/TSSOP/.0255/16/WB.220/L.210/IPC-7351 (2005)/NORMAL]
U15  A2982  [SM/SOIC.050/20/WB.300/L.510/IPC-7351 (2005)/NORMAL]
sheet B3B4
C41  1uF/50V  [CYL/D.320/LS.140/.076/.034/IPC-7351 (2005)/NORMAL]
C42  1uF/50V  [CYL/D.320/LS.140/.076/.034/IPC-7351 (2005)/NORMAL]
C43  100nF  [C/SM/0805/IPC-7351 (2005)/NORMAL]
C44  100nF  [C/SM/0805/IPC-7351 (2005)/NORMAL]
C45  1uF/50V  [CYL/D.320/LS.140/.076/.034/IPC-7351 (2005)/NORMAL]
C46  1uF/50V  [CYL/D.320/LS.140/.076/.034/IPC-7351 (2005)/NORMAL]
C47  100nF  [C/SM/0805/IPC-7351 (2005)/NORMAL]
C48  100nF  [C/SM/0805/IPC-7351 (2005)/NORMAL]
C49  1uF/50V  [CYL/D.320/LS.140/.076/.034/IPC-7351 (2005)/NORMAL]
C50  1uF/50V  [CYL/D.320/LS.140/.076/.034/IPC-7351 (2005)/NORMAL]
C51  100nF  [C/SM/0805/IPC-7351 (2005)/NORMAL]
C52  100nF  [C/SM/0805/IPC-7351 (2005)/NORMAL]
C53  1uF/50V  [CYL/D.320/LS.140/.076/.034/IPC-7351 (2005)/NORMAL]
C54  1uF/50V  [CYL/D.320/LS.140/.076/.034/IPC-7351 (2005)/NORMAL]
C55  100nF  [C/SM/0805/IPC-7351 (2005)/NORMAL]
C56  100nF  [C/SM/0805/IPC-7351 (2005)/NORMAL]
C57  100nF  [C/SM/0805/IPC-7351 (2005)/NORMAL]
D7  1N4148  [SM/SOD123/IPC-7351 (2005)/NORMAL]
D8  1N4148  [SM/SOD123/IPC-7351 (2005)/NORMAL]
D9  1N4148  [SM/SOD123/IPC-7351 (2005)/NORMAL]
D10  1N4148  [SM/SOD123/IPC-7351 (2005)/NORMAL]
D11  1N4148  [SM/SOD123/IPC-7351 (2005)/NORMAL]
D12  1N4148  [SM/SOD123/IPC-7351 (2005)/NORMAL]
D13  1N4148  [SM/SOD123/IPC-7351 (2005)/NORMAL]
D14  1N4148  [SM/SOD123/IPC-7351 (2005)/NORMAL]
R58  360R/0.66W/5%  [R/SM/1206/IPC-7351 (2005)/NORMAL]
R59  1k2  [R/SM/0805/IPC-7351 (2005)/NORMAL]
R60  360R/0.66W/5%  [R/SM/1206/IPC-7351 (2005)/NORMAL]
R61  1k2  [R/SM/0805/IPC-7351 (2005)/NORMAL]
R62  2k  [R/SM/0805/IPC-7351 (2005)/NORMAL]
R63  2k  [R/SM/0805/IPC-7351 (2005)/NORMAL]
R64  360R/0.66W/5%  [R/SM/1206/IPC-7351 (2005)/NORMAL]
R65  360R/0.66W/5%  [R/SM/1206/IPC-7351 (2005)/NORMAL]
R66  360R/0.66W/5%  [R/SM/1206/IPC-7351 (2005)/NORMAL]
R67  1k2  [R/SM/0805/IPC-7351 (2005)/NORMAL]
R68  360R/0.66W/5%  [R/SM/1206/IPC-7351 (2005)/NORMAL]
R69  1k2  [R/SM/0805/IPC-7351 (2005)/NORMAL]
R70  2k  [R/SM/0805/IPC-7351 (2005)/NORMAL]
R71  2k  [R/SM/0805/IPC-7351 (2005)/NORMAL]
R72  360R/0.66W/5%  [R/SM/1206/IPC-7351 (2005)/NORMAL]
R73  360R/0.66W/5%  [R/SM/1206/IPC-7351 (2005)/NORMAL]
R74  360R/0.66W/5%  [R/SM/1206/IPC-7351 (2005)/NORMAL]
R75  1k2  [R/SM/0805/IPC-7351 (2005)/NORMAL]
R76  360R/0.66W/5%  [R/SM/1206/IPC-7351 (2005)/NORMAL]
R77  1k2  [R/SM/0805/IPC-7351 (2005)/NORMAL]
R78  2k  [R/SM/0805/IPC-7351 (2005)/NORMAL]
R79  2k  [R/SM/0805/IPC-7351 (2005)/NORMAL]
R80  360R/0.66W/5%  [R/SM/1206/IPC-7351 (2005)/NORMAL]
R81  360R/0.66W/5%  [R/SM/1206/IPC-7351 (2005)/NORMAL]
R82  360R/0.66W/5%  [R/SM/1206/IPC-7351 (2005)/NORMAL]
R83  1k2  [R/SM/0805/IPC-7351 (2005)/NORMAL]
R84  360R/0.66W/5%  [R/SM/1206/IPC-7351 (2005)/NORMAL]
R85  1k2  [R/SM/0805/IPC-7351 (2005)/NORMAL]
R86  2k  [R/SM/0805/IPC-7351 (2005)/NORMAL]
R87  2k  [R/SM/0805/IPC-7351 (2005)/NORMAL]
R88  360R/0.66W/5%  [R/SM/1206/IPC-7351 (2005)/NORMAL]
R89  360R/0.66W/5%  [R/SM/1206/IPC-7351 (2005)/NORMAL]
R90  4k7  [R/SM/0805/IPC-7351 (2005)/NORMAL]
TVS26  SMAJ10A  [SM/DO214AC/IPC-7351 (2005)/NORMAL]
TVS27  SMAJ10A  [SM/DO214AC/IPC-7351 (2005)/NORMAL]
TVS28  SMAJ10A  [SM/DO214AC/IPC-7351 (2005)/NORMAL]
TVS29  SMAJ10A  [SM/DO214AC/IPC-7351 (2005)/NORMAL]
TVS30  SMAJ10A  [SM/DO214AC/IPC-7351 (2005)/NORMAL]
TVS31  SMAJ10A  [SM/DO214AC/IPC-7351 (2005)/NORMAL]
TVS32  SMAJ10A  [SM/DO214AC/IPC-7351 (2005)/NORMAL]
TVS33  SMAJ10A  [SM/DO214AC/IPC-7351 (2005)/NORMAL]
U16  FODM8071  [SM/SOIC.050/05/WB.180/L.170/IPC-7351 (2005)/NORMAL]
U17  FODM8071  [SM/SOIC.050/05/WB.180/L.170/IPC-7351 (2005)/NORMAL]
U18  FODM8071  [SM/SOIC.050/05/WB.180/L.170/IPC-7351 (2005)/NORMAL]
U19  FODM8071  [SM/SOIC.050/05/WB.180/L.170/IPC-7351 (2005)/NORMAL]
U20  FODM8071  [SM/SOIC.050/05/WB.180/L.170/IPC-7351 (2005)/NORMAL]
U21  FODM8071  [SM/SOIC.050/05/WB.180/L.170/IPC-7351 (2005)/NORMAL]
U22  FODM8071  [SM/SOIC.050/05/WB.180/L.170/IPC-7351 (2005)/NORMAL]
U23  FODM8071  [SM/SOIC.050/05/WB.180/L.170/IPC-7351 (2005)/NORMAL]
U24  TCA9538  [SM/TSSOP/.0255/16/WB.220/L.210/IPC-7351 (2005)/NORMAL]
sheet B5
C296  100uF/50V  [CYL/D.400/LS.200/.076/.034/IPC-7351 (2005)/NORMAL]
C297  1uF  [C/SM/1206/IPC-7351 (2005)/NORMAL]
C298  10uF/25V  [C/SM/1210/IPC-7351 (2005)/NORMAL]
C299  100nF  [R/SM/0805/IPC-7351 (2005)/NORMAL]
L7  BLM41PG102  [L/SM/CHIP/1806/IPC-7351 (2005)/NORMAL]
R323  RXEF005  [DISC/.200X.050/LS.320X.150/.064/.030/IPC-7351 (2005)/NORMAL]
R324  75k  [R/SM/0805/IPC-7351 (2005)/NORMAL]
TVS34  SMAJ15A  [SM/DO214AC/IPC-7351 (2005)/NORMAL]
U94  LT3082  [SM/SOT223]
X19  69167-105HLF  [CONN/69167/05/.100/.064]
X20  69167-105HLF  [CONN/69167/05/.100/.064]
X21  69167-105HLF  [CONN/69167/05/.100/.064]
X22  69167-105HLF  [CONN/69167/05/.100/.064]
X23  69167-105HLF  [CONN/69167/05/.100/.064]
X24  69167-105HLF  [CONN/69167/05/.100/.064]
X25  69167-105HLF  [CONN/69167/05/.100/.064]
sheet B5B1
C300  100nF  [C/SM/0805/IPC-7351 (2005)/NORMAL]
C301  100nF  [C/SM/0805/IPC-7351 (2005)/NORMAL]
C302  100nF  [C/SM/0805/IPC-7351 (2005)/NORMAL]
C303  100nF  [C/SM/0805/IPC-7351 (2005)/NORMAL]
R325  150k  [R/SM/0805/IPC-7351 (2005)/NORMAL]
R326  5k1  [R/SM/0805/IPC-7351 (2005)/NORMAL]
R327  2k7  [R/SM/0805/IPC-7351 (2005)/NORMAL]
R328  20k  [R/SM/0805/IPC-7351 (2005)/NORMAL]
R329  20k  [R/SM/0805/IPC-7351 (2005)/NORMAL]
R330  1k3  [R/SM/0805/IPC-7351 (2005)/NORMAL]
R331  150k  [R/SM/0805/IPC-7351 (2005)/NORMAL]
R332  5k1  [R/SM/0805/IPC-7351 (2005)/NORMAL]
R333  2k7  [R/SM/0805/IPC-7351 (2005)/NORMAL]
R334  20k  [R/SM/0805/IPC-7351 (2005)/NORMAL]
R335  1k3  [R/SM/0805/IPC-7351 (2005)/NORMAL]
R336  20k  [R/SM/0805/IPC-7351 (2005)/NORMAL]
TVS35  SMAJ5.0A  [SM/DO214AC/IPC-7351 (2005)/NORMAL]
TVS36  SMAJ5.0A  [SM/DO214AC/IPC-7351 (2005)/NORMAL]
U95  TLV1701  [SM/SOT23/5/IPC-7351 (2005)/NORMAL]
U96  TLV1701  [SM/SOT23/5/IPC-7351 (2005)/NORMAL]
sheet B5B2
C304  100nF  [C/SM/0805/IPC-7351 (2005)/NORMAL]
C305  100nF  [C/SM/0805/IPC-7351 (2005)/NORMAL]
C306  100nF  [C/SM/0805/IPC-7351 (2005)/NORMAL]
C307  100nF  [C/SM/0805/IPC-7351 (2005)/NORMAL]
R337  150k  [R/SM/0805/IPC-7351 (2005)/NORMAL]
R338  5k1  [R/SM/0805/IPC-7351 (2005)/NORMAL]
R339  2k7  [R/SM/0805/IPC-7351 (2005)/NORMAL]
R340  20k  [R/SM/0805/IPC-7351 (2005)/NORMAL]
R341  1k3  [R/SM/0805/IPC-7351 (2005)/NORMAL]
R342  20k  [R/SM/0805/IPC-7351 (2005)/NORMAL]
R343  150k  [R/SM/0805/IPC-7351 (2005)/NORMAL]
R344  5k1  [R/SM/0805/IPC-7351 (2005)/NORMAL]
R345  2k7  [R/SM/0805/IPC-7351 (2005)/NORMAL]
R346  20k  [R/SM/0805/IPC-7351 (2005)/NORMAL]
R347  1k3  [R/SM/0805/IPC-7351 (2005)/NORMAL]
R348  20k  [R/SM/0805/IPC-7351 (2005)/NORMAL]
TVS37  SMAJ5.0A  [SM/DO214AC/IPC-7351 (2005)/NORMAL]
TVS38  SMAJ5.0A  [SM/DO214AC/IPC-7351 (2005)/NORMAL]
U97  TLV1701  [SM/SOT23/5/IPC-7351 (2005)/NORMAL]
U98  TLV1701  [SM/SOT23/5/IPC-7351 (2005)/NORMAL]
sheet B5B4
C312  100nF  [C/SM/0805/IPC-7351 (2005)/NORMAL]
C313  100nF  [C/SM/0805/IPC-7351 (2005)/NORMAL]
C314  100nF  [C/SM/0805/IPC-7351 (2005)/NORMAL]
C315  100nF  [C/SM/0805/IPC-7351 (2005)/NORMAL]
R361  150k  [R/SM/0805/IPC-7351 (2005)/NORMAL]
R362  2k7  [R/SM/0805/IPC-7351 (2005)/NORMAL]
R363  20k  [R/SM/0805/IPC-7351 (2005)/NORMAL]
R364  5k1  [R/SM/0805/IPC-7351 (2005)/NORMAL]
R365  1k3  [R/SM/0805/IPC-7351 (2005)/NORMAL]
R366  20k  [R/SM/0805/IPC-7351 (2005)/NORMAL]
R367  150k  [R/SM/0805/IPC-7351 (2005)/NORMAL]
R368  5k1  [R/SM/0805/IPC-7351 (2005)/NORMAL]
R369  2k7  [R/SM/0805/IPC-7351 (2005)/NORMAL]
R370  20k  [R/SM/0805/IPC-7351 (2005)/NORMAL]
R371  1k3  [R/SM/0805/IPC-7351 (2005)/NORMAL]
R372  20k  [R/SM/0805/IPC-7351 (2005)/NORMAL]
TVS41  SMAJ5.0A  [SM/DO214AC/IPC-7351 (2005)/NORMAL]
TVS42  SMAJ5.0A  [SM/DO214AC/IPC-7351 (2005)/NORMAL]
U101  TLV1701  [SM/SOT23/5/IPC-7351 (2005)/NORMAL]
U102  TLV1701  [SM/SOT23/5/IPC-7351 (2005)/NORMAL]
sheet B5B5
C316  100nF  [C/SM/0805/IPC-7351 (2005)/NORMAL]
C317  100nF  [C/SM/0805/IPC-7351 (2005)/NORMAL]
C318  100nF  [C/SM/0805/IPC-7351 (2005)/NORMAL]
C319  100nF  [C/SM/0805/IPC-7351 (2005)/NORMAL]
R373  150k  [R/SM/0805/IPC-7351 (2005)/NORMAL]
R374  5k1  [R/SM/0805/IPC-7351 (2005)/NORMAL]
R375  2k7  [R/SM/0805/IPC-7351 (2005)/NORMAL]
R376  20k  [R/SM/0805/IPC-7351 (2005)/NORMAL]
R377  1k3  [R/SM/0805/IPC-7351 (2005)/NORMAL]
R378  20k  [R/SM/0805/IPC-7351 (2005)/NORMAL]
R379  150k  [R/SM/0805/IPC-7351 (2005)/NORMAL]
R380  5k1  [R/SM/0805/IPC-7351 (2005)/NORMAL]
R381  2k7  [R/SM/0805/IPC-7351 (2005)/NORMAL]
R382  20k  [R/SM/0805/IPC-7351 (2005)/NORMAL]
R383  1k3  [R/SM/0805/IPC-7351 (2005)/NORMAL]
R384  20k  [R/SM/0805/IPC-7351 (2005)/NORMAL]
TVS43  SMAJ5.0A  [SM/DO214AC/IPC-7351 (2005)/NORMAL]
TVS44  SMAJ5.0A  [SM/DO214AC/IPC-7351 (2005)/NORMAL]
U103  TLV1701  [SM/SOT23/5/IPC-7351 (2005)/NORMAL]
U104  TLV1701  [SM/SOT23/5/IPC-7351 (2005)/NORMAL]
sheet B5B6
C320  100nF  [C/SM/0805/IPC-7351 (2005)/NORMAL]
C321  100nF  [C/SM/0805/IPC-7351 (2005)/NORMAL]
C322  100nF  [C/SM/0805/IPC-7351 (2005)/NORMAL]
C323  100nF  [C/SM/0805/IPC-7351 (2005)/NORMAL]
R385  150k  [R/SM/0805/IPC-7351 (2005)/NORMAL]
R386  5k1  [R/SM/0805/IPC-7351 (2005)/NORMAL]
R387  2k7  [R/SM/0805/IPC-7351 (2005)/NORMAL]
R388  20k  [R/SM/0805/IPC-7351 (2005)/NORMAL]
R389  1k3  [R/SM/0805/IPC-7351 (2005)/NORMAL]
R390  20k  [R/SM/0805/IPC-7351 (2005)/NORMAL]
R391  150k  [R/SM/0805/IPC-7351 (2005)/NORMAL]
R392  5k1  [R/SM/0805/IPC-7351 (2005)/NORMAL]
R393  2k7  [R/SM/0805/IPC-7351 (2005)/NORMAL]
R394  20k  [R/SM/0805/IPC-7351 (2005)/NORMAL]
R395  1k3  [R/SM/0805/IPC-7351 (2005)/NORMAL]
R396  20k  [R/SM/0805/IPC-7351 (2005)/NORMAL]
TVS45  SMAJ5.0A  [SM/DO214AC/IPC-7351 (2005)/NORMAL]
TVS46  SMAJ5.0A  [SM/DO214AC/IPC-7351 (2005)/NORMAL]
U105  TLV1701  [SM/SOT23/5/IPC-7351 (2005)/NORMAL]
U106  TLV1701  [SM/SOT23/5/IPC-7351 (2005)/NORMAL]

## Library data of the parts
+3V3D +5VD +24V = TEST_POINT
C1 C8 = CAP_POL: MFR. P/N: MAL214658681E3; RS: 684-1826
C2 C7 C9 C33 C34 C36 C37 C39 C40 C43 C44 C47 C48 C51 C52 C55-C57 C299-C307 C312-C323 = CAP_NP: RS: 723-5058
C3 C10 = CAP_POL: MFR. P/N: T591D227M010ATE025; RS: 888-1973
C4 C12 = CAP_NP: RS: 723-6196
C5 C11 = CAP_NP: RS: 624-2519
C6 = CAP_NP: RS: 723-6401
D1 D2 = DIODE_SCHOTTKY: MFR. P/N: MBRS360BT3G; RS: 792-5653
L1 = INDUCTOR: RS: 744-4860
L2 = INDUCTOR: RS: 124-1890
LED1-LED3 = LED: RS: 654-5773
R1 = R_PTC_(H): RS: 517-6691
R2 R3 R6-R10 R12 R15 R16 R34 R43 R52 R59 R61-R63 R67 R69-R71 R75 R77-R79 R83 R85-R87 R90 R324-R348 R361-R396 = R
R4 = R: RS: 708-6060
R5 R13 = R: RS: 828-0780
R11 = R: RS: 828-0639
R14 = R: RS: 721-9879
TVS1 = DIODE_ZENER_1: RS: 764-5694
U1 U3 = LM2599: MFR. P/N: LM2599S-ADJ/NOPB; RS: 761-4993
U2 U95-U98 U101-U106 = TLV1701: MFR. P/N: TLV1701AIDBV; RS: 900-9879
JX1 JX2 = HEADER_50X2: Farnell: 1103987; MFR. P/N: 61083-104400LF
C32 C35 C38 = CAP_POL: RS: 888-1958
R33 R35-R42 R44-R51 R53-R57 R323 = R_PTC_(H): RS: 517-6556
TVS4-TVS25 = DIODE_ZENER_1: RS: 764-5540
U10 U12 U14 U24 = TCA9538: MFR. P/N: TCA9538DBR; RS: 133-0706
U11 U13 U15 = A2982: MFR. P/N: A2982SLWTR-T; RS: 680-7220
C41 C42 C45 C46 C49 C50 C53 C54 = CAP_POL: RS: 762-1764
D7-D14 = 1N4148: MFR. P/N: 1N4148W-E3-08; RS: 700-3671
R58 R60 R64-R66 R68 R72-R74 R76 R80-R82 R84 R88 R89 = R: RS: 721-9787
TVS26-TVS33 = DIODE_ZENER_1: RS: 822-8528
U16-U23 = FODM8071: RS: 739-4992
C296 = CAP_POL: RS: 684-1762
C297 = CAP_NP: RS: 723-6584
C298 = CAP_NP: RS: 790-0632
L7 = CHOKE_IRON: RS: 724-1598
TVS34 = DIODE_ZENER_1: RS: 764-5537
U94 = LT3088_3: MFR. P/N: LT3082IST#PBF; RS: 858-0793
X19-X25 = MOLEX_5: RS: 863-3204
TVS35-TVS38 TVS41-TVS46 = DIODE_ZENER_1: RS: 764-5565

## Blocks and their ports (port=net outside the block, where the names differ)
Drivers IGBT/Chopper Freno = schematic B5B4 Chopper Freno, on sheet B5: DRIVER_UP_15V=Drivers IGBT/N42060, DRIVER_DOWN_15V=Drivers IGBT/N42064, DRIVER_DOWN_3V3=N09627, DRIVER_UP_3V3=N09623
Drivers IGBT/Generador fase T = schematic B5B1Generador fase T, on sheet B5: DRIVER_UP_15V=Drivers IGBT/N34200, DRIVER_DOWN_15V=Drivers IGBT/N34204, DRIVER_DOWN_3V3=N09557, DRIVER_UP_3V3=N09545
Drivers IGBT/Red fase T = schematic B5B5 Red fase T, on sheet B5: DRIVER_UP_15V=Drivers IGBT/N35539, DRIVER_DOWN_15V=Drivers IGBT/N35543, DRIVER_DOWN_3V3=N09651, DRIVER_UP_3V3=N09647
Drivers IGBT/Red fase R = schematic B5B7 Red fase R, on sheet B5: DRIVER_UP_15V=Drivers IGBT/N35353, DRIVER_DOWN_15V=Drivers IGBT/N35357, DRIVER_DOWN_3V3=N09699, DRIVER_UP_3V3=N09695
Drivers IGBT/Generador fase S = schematic B5B2 Generador fase S, on sheet B5: DRIVER_UP_15V=Drivers IGBT/N34773, DRIVER_DOWN_15V=Drivers IGBT/N34777, DRIVER_DOWN_3V3=N09579, DRIVER_UP_3V3=N09575
Drivers IGBT/Red fase S = schematic B5B6 Red fase S, on sheet B5: DRIVER_UP_15V=Drivers IGBT/N35589, DRIVER_DOWN_15V=Drivers IGBT/N35593, DRIVER_DOWN_3V3=N09675, DRIVER_UP_3V3=N09671
Drivers IGBT/Generador fase R = schematic B5B3 Generador fase R, on sheet B5: DRIVER_UP_15V=Drivers IGBT/N34883, DRIVER_DOWN_15V=Drivers IGBT/N34887, DRIVER_DOWN_3V3=N09603, DRIVER_UP_3V3=N09599

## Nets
+3V3D: +3V3D.1 C3.1 C301.2 C303.2 C305.2 C307.2 C313.2 C315.2 C317.2 C319.2 C321.2 C323.2 JX1.78 JX1.79 JX1.80 JX2.78 JX2.79 JX2.80 JX2.98 L1.1 R2.2 R4.1 R6.1 R16.2 R90.2 R326.2 R332.2 R338.2 R344.2 R364.2 R368.2 R374.2 R380.2 R386.2 R392.2 U10.16(Vcc) U12.1(A0) U12.16(Vcc) U14.2(A1) U14.16(Vcc) U24.16(Vcc) ; also on sheet 37 38
+5VD: +5VD.1 C7.2 C10.1 JX1.57 JX1.58 JX1.59 JX1.60 JX2.12 JX2.57 JX2.58 JX2.59 JX2.60 L2.1 R9.2 R11.1 R12.1 R15.2 U2.5(+V)
+15Vd: C296.1 C300.2 C302.2 C304.2 C306.2 C312.2 C314.2 C316.2 C318.2 C320.2 C322.2 L7.2 R323.2 TVS34.1(CATHODE) U95.5(+V) U96.5(+V) U97.5(+V) U98.5(+V) U101.5(+V) U102.5(+V) U103.5(+V) U104.5(+V) U105.5(+V) U106.5(+V) ; also on sheet 37 38
+15VdP: R323.1 X19.1 X20.1 X21.1 X22.1 X23.1 X24.1 X25.1
+24V: +24V.1 C1.1 C2.2 C8.1 C9.2 R1.2 R14.2 R58.2 R60.2 R66.2 R68.2 R74.2 R76.2 R82.2 R84.2 TVS1.1(CATHODE) U1.1(VIN) U3.1(VIN) U11.9(+Vs) U13.9(+Vs) U15.9(+Vs) ; also on sheet 24
+24VP: R1.1
GND_ANALOG: C1.2 C2.1 C3.2 C4.1 C6.1 C7.1 C8.2 C9.1 C10.2 C12.1 C296.2 C297.2 C298.2 C299.1 C300.1 C301.1 C302.1 C303.1 C304.1 C305.1 C306.1 C307.1 C312.1 C313.1 C314.1 C315.1 C316.1 C317.1 C318.1 C319.1 C320.1 C321.1 C322.1 C323.1 D1.2(ANODE) D2.2(ANODE) JX1.15 JX1.16 JX1.21 JX1.22 JX1.27 JX1.28 JX1.33 JX1.34 JX1.39 JX1.40 JX1.45 JX1.46 JX1.51 JX1.52 JX1.65 JX1.66 JX1.71 JX1.72 JX1.77 JX1.85 JX1.86 JX1.95 JX1.96 JX2.15 JX2.16 JX2.21 JX2.22 JX2.27 JX2.28 JX2.33 JX2.34 JX2.39 JX2.40 JX2.45 JX2.46 JX2.51 JX2.52 JX2.65 JX2.66 JX2.71 JX2.72 JX2.77 JX2.85 JX2.86 JX2.91 JX2.92 LED1.1(CATHODE) LED2.1(CATHODE) LED3.1(CATHODE) R5.1 R10.1 R13.1 R324.2 R330.1 R335.1 R341.1 R347.1 R365.1 R371.1 R377.1 R383.1 R389.1 R395.1 TVS1.2(ANODE) TVS34.2(ANODE) TVS35.2(ANODE) TVS36.2(ANODE) TVS37.2(ANODE) TVS38.2(ANODE) TVS41.2(ANODE) TVS42.2(ANODE) TVS43.2(ANODE) TVS44.2(ANODE) TVS45.2(ANODE) TVS46.2(ANODE) U1.4(GND) U1.8(GND) U2.2(-V) U3.4(GND) U3.8(GND) U95.2(-V) U96.2(-V) U97.2(-V) U98.2(-V) U101.2(-V) U102.2(-V) U103.2(-V) U104.2(-V) U105.2(-V) U106.2(-V) X19.4 X20.4 X21.4 X22.4 X23.4 X24.4 X25.4 ; also on sheet 2 3 4 5 6 7 8 9 10 11 12 13 14 15 16 17 18 19 20 21 22 24 37 38
GND_DIGI: C32.2 C33.1 C34.1 C35.2 C36.1 C37.1 C38.2 C39.1 C40.1 C43.1 C44.1 C47.1 C48.1 C51.1 C52.1 C55.1 C56.1 C57.1 TVS4.2(ANODE) TVS5.2(ANODE) TVS6.2(ANODE) TVS7.2(ANODE) TVS8.2(ANODE) TVS9.2(ANODE) TVS10.2(ANODE) TVS11.2(ANODE) TVS12.2(ANODE) TVS13.2(ANODE) TVS14.2(ANODE) TVS15.2(ANODE) TVS16.2(ANODE) TVS17.2(ANODE) TVS18.2(ANODE) TVS19.2(ANODE) TVS20.2(ANODE) TVS21.2(ANODE) TVS22.2(ANODE) TVS23.2(ANODE) TVS24.2(ANODE) TVS25.2(ANODE) U10.1(A0) U10.2(A1) U10.8(GND) U11.12(GND) U12.2(A1) U12.8(GND) U13.12(GND) U14.1(A0) U14.8(GND) U15.12(GND) U16.4(GND) U17.4(GND) U18.4(GND) U19.4(GND) U20.4(GND) U21.4(GND) U22.4(GND) U23.4(GND) U24.1(A0) U24.2(A1) U24.8(GND)
VCC_CIRCLE: C32.1 C33.2 C34.2 C35.1 C36.2 C37.2 C38.1 C39.2 C40.2 C43.2 C44.2 C47.2 C48.2 C51.2 C52.2 C55.2 C56.2 C57.2 R34.2 R43.2 R52.2 U16.6(Vdd) U17.6(Vdd) U18.6(Vdd) U19.6(Vdd) U20.6(Vdd) U21.6(Vdd) U22.6(Vdd) U23.6(Vdd) ; also on sheet 2 3 4 5 6 7 8 9 10 11 12 13 14 15 16 17 18 19 20 21 22
DAC_D0: JX2.43 ; also on sheet 18
DAC_D1: JX2.89 ; also on sheet 18
DAC_D2: JX2.88 ; also on sheet 18
DAC_D3: JX2.54 ; also on sheet 18
DAC_D4: JX2.44 ; also on sheet 18
DAC_D5: JX2.17 ; also on sheet 18
DAC_D6: JX2.23 ; also on sheet 18
DAC_D7: JX2.29 ; also on sheet 18
DAC_D8: JX2.25 ; also on sheet 18
DAC_D9: JX2.19 ; also on sheet 18
DAC_D10: JX2.20 ; also on sheet 18
DAC_D11: JX2.50 ; also on sheet 18
DAC_D12: JX2.84 ; also on sheet 18
DAC_D13: JX2.90 ; also on sheet 18
DAC_D14: JX2.83 ; also on sheet 18
DAC_D15: JX2.41 ; also on sheet 18
DAC_D16: JX2.35 ; also on sheet 18
DAC_SCLK0: JX2.31 ; also on sheet 18
DAC_SCLK1: JX2.18 ; also on sheet 18
DAC_SCLK2: JX2.48 ; also on sheet 18
DAC_SCLK3: JX2.82 ; also on sheet 18
DAC_SCLK4: JX2.37 ; also on sheet 18
DAC_SCLK5: JX2.87 ; also on sheet 18
DI_/INT: R90.1 U24.13(/INT)
DI_RST: U24.3(/RESET)
DI_SCL: U24.14(SCL)
DI_SDA: U24.15(SDA)
DIG_IN0: R64.2
DIG_IN1: R65.2
DIG_IN2: R72.2
DIG_IN3: R73.2
DIG_IN4: R80.2
DIG_IN5: R81.2
DIG_IN6: R88.2
DIG_IN7: R89.2
DIG_OUT0: R33.2
DIG_OUT1: R35.2
DIG_OUT2: R36.2
DIG_OUT3: R37.2
DIG_OUT4: R38.2
DIG_OUT5: R39.2
DIG_OUT6: R40.2
DIG_OUT7: R41.2
DIG_OUT8: R42.2
DIG_OUT9: R44.2
DIG_OUT10: R45.2
DIG_OUT11: R46.2
DIG_OUT12: R47.2
DIG_OUT13: R48.2
DIG_OUT14: R49.2
DIG_OUT15: R50.2
DIG_OUT16: R51.2
DIG_OUT17: U14.5(P1)
DIG_OUT18: R53.2
DIG_OUT19: R54.2
DIG_OUT20: R55.2
DIG_OUT21: R56.2
DIG_OUT22: R57.2
DO_RST: U10.3(/RESET) U12.3(/RESET) U14.3(/RESET)
DO_SCL: U10.14(SCL) U12.14(SCL) U14.14(SCL)
DO_SDA: U10.15(SDA) U12.15(SDA) U14.15(SDA)
IF MicroZed/JX1_LVDS_5_N: JX1.26
IF MicroZed/JX1_LVDS_5_P: JX1.24
IF MicroZed/JX1_LVDS_9_N: JX1.38
IF MicroZed/JX1_LVDS_9_P: JX1.36
IF MicroZed/JX1_LVDS_11_N: JX1.44
IF MicroZed/JX1_LVDS_11_P: JX1.42
IF MicroZed/JX1_LVDS_13_N: JX1.50
IF MicroZed/JX1_LVDS_13_P: JX1.48
IF MicroZed/JX1_LVDS_14_N: JX1.55
IF MicroZed/JX1_LVDS_15_N: JX1.56
IF MicroZed/JX1_LVDS_15_P: JX1.54
IF MicroZed/JX1_LVDS_16_P: JX1.61
IF MicroZed/JX1_LVDS_17_N: JX1.64
IF MicroZed/JX1_LVDS_17_P: JX1.62
IF MicroZed/JX1_LVDS_19_N: JX1.70
IF MicroZed/JX1_LVDS_20_P: JX1.73
IF MicroZed/JX1_LVDS_23_N: JX1.84
IF MicroZed/JX1_LVDS_23_P: JX1.82
IF MicroZed/JX2_LVDS_3_N: JX2.26
IF MicroZed/JX2_LVDS_3_P: JX2.24
IF MicroZed/JX2_LVDS_5_N: JX2.32
IF MicroZed/JX2_LVDS_5_P: JX2.30
IF MicroZed/JX2_LVDS_7_N: JX2.38
IF MicroZed/JX2_LVDS_7_P: JX2.36
IF MicroZed/JX2_LVDS_9_P: JX2.42
IF MicroZed/JX2_LVDS_10_N: JX2.49
IF MicroZed/JX2_LVDS_10_P: JX2.47
IF MicroZed/JX2_LVDS_12_N: JX2.55
IF MicroZed/JX2_LVDS_12_P: JX2.53
IF MicroZed/JX2_LVDS_13_N: JX2.56
IF MicroZed/JX2_LVDS_14_N: JX2.63
IF MicroZed/JX2_LVDS_14_P: JX2.61
IF MicroZed/JX2_LVDS_15_N: JX2.64
IF MicroZed/JX2_LVDS_15_P: JX2.62
IF MicroZed/JX2_LVDS_16_N: JX2.69
IF MicroZed/JX2_LVDS_16_P: JX2.67
IF MicroZed/JX2_LVDS_17_N: JX2.70
IF MicroZed/JX2_LVDS_17_P: JX2.68
IF MicroZed/JX2_LVDS_18_N: JX2.75
IF MicroZed/JX2_LVDS_18_P: JX2.73
IF MicroZed/JX2_LVDS_19_P: JX2.74
IF MicroZed/JX2_LVDS_20_P: JX2.81
NTC_D0: JX1.18
NTC_D1: JX1.30
NTC_D2: JX1.20
NTC_D3: JX1.32
Vth: C298.1 R329.2 R336.2 R342.2 R348.2 R366.2 R372.2 R378.2 R384.2 R390.2 R396.2 U94.2(OUT) U94.4(OUT) ; also on sheet 37 38
Alimentacion/Alimentacion Digital/N29099: R3.2 R7.1 U2.1(+)
Alimentacion/Alimentacion Digital/N29127: R3.1 R8.2 U2.4(Out)
Alimentacion/Alimentacion Digital/N29195: R9.1 R10.2 U2.3(-)
Alimentacion/Alimentacion Digital/N29325: C5.2 R4.2 R5.2 U1.6(FB)
Alimentacion/Alimentacion Digital/N29333: D1.1(CATHODE) L1.2 U1.2(OUT)
Alimentacion/Alimentacion Digital/N29513: C5.1 R6.2
Alimentacion/Alimentacion Digital/N29585: C6.2 R8.1 U1.7(SS)
Alimentacion/Alimentacion Digital/N29597: C4.2 U1.5(DELAY)
Alimentacion/Alimentacion Digital/N37464: C11.2 R11.2 R13.2 U3.6(FB)
Alimentacion/Alimentacion Digital/N37504: D2.1(CATHODE) L2.2 U3.2(OUT)
Alimentacion/Alimentacion Digital/N37676: C11.1 R12.2
Alimentacion/Alimentacion Digital/N37748: C12.2 U3.7(SS)
Drivers IGBT/Chopper Freno/N32292: R362.1 R363.2 R365.2 TVS41.1(CATHODE)
Drivers IGBT/Chopper Freno/N32296: R361.2 R363.1 U101.1(+)
Drivers IGBT/Chopper Freno/N32400: R366.1 U101.3(-)
Drivers IGBT/Chopper Freno/N33120: R369.1 R370.2 R371.2 TVS42.1(CATHODE)
Drivers IGBT/Chopper Freno/N33124: R367.2 R370.1 U102.1(+)
Drivers IGBT/Chopper Freno/N33228: R372.1 U102.3(-)
Drivers IGBT/Generador fase S/N35234: R339.1 R340.2 R341.2 TVS37.1(CATHODE)
Drivers IGBT/Generador fase S/N35238: R337.2 R340.1 U97.1(+)
Drivers IGBT/Generador fase S/N35342: R342.1 U97.3(-)
Drivers IGBT/Generador fase S/N35592: R345.1 R346.2 R347.2 TVS38.1(CATHODE)
Drivers IGBT/Generador fase S/N35612: R343.2 R346.1 U98.1(+)
Drivers IGBT/Generador fase S/N35696: R348.1 U98.3(-)
Drivers IGBT/Generador fase T/N33990: R327.1 R328.2 R330.2 TVS35.1(CATHODE)
Drivers IGBT/Generador fase T/N33994: R325.2 R328.1 U95.1(+)
Drivers IGBT/Generador fase T/N34098: R329.1 U95.3(-)
Drivers IGBT/Generador fase T/N34364: R333.1 R334.2 R335.2 TVS36.1(CATHODE)
Drivers IGBT/Generador fase T/N34368: R331.2 R334.1 U96.1(+)
Drivers IGBT/Generador fase T/N34456: R336.1 U96.3(-)
Drivers IGBT/N34200: R327.2 X19.2
Drivers IGBT/N34204: R333.2 X19.3
Drivers IGBT/N34773: R339.2 X20.2
Drivers IGBT/N34777: R345.2 X20.3
Drivers IGBT/N34883: X21.2 ; also on sheet 38
Drivers IGBT/N34887: X21.3 ; also on sheet 38
Drivers IGBT/N35353: X25.2 ; also on sheet 37
Drivers IGBT/N35357: X25.3 ; also on sheet 37
Drivers IGBT/N35539: R375.2 X23.2
Drivers IGBT/N35543: R381.2 X23.3
Drivers IGBT/N35589: R387.2 X24.2
Drivers IGBT/N35593: R393.2 X24.3
Drivers IGBT/N42060: R362.2 X22.2
Drivers IGBT/N42064: R369.2 X22.3
Drivers IGBT/N43590: C299.2 R324.1 U94.1(SET)
Drivers IGBT/N43668: C297.1 L7.1 U94.3(VIN)
Drivers IGBT/Red fase S/N35234: R387.1 R388.2 R389.2 TVS45.1(CATHODE)
Drivers IGBT/Red fase S/N35238: R385.2 R388.1 U105.1(+)
Drivers IGBT/Red fase S/N35342: R390.1 U105.3(-)
Drivers IGBT/Red fase S/N35592: R393.1 R394.2 R395.2 TVS46.1(CATHODE)
Drivers IGBT/Red fase S/N35612: R391.2 R394.1 U106.1(+)
Drivers IGBT/Red fase S/N35696: R396.1 U106.3(-)
Drivers IGBT/Red fase T/N35234: R375.1 R376.2 R377.2 TVS43.1(CATHODE)
Drivers IGBT/Red fase T/N35238: R373.2 R376.1 U103.1(+)
Drivers IGBT/Red fase T/N35342: R378.1 U103.3(-)
Drivers IGBT/Red fase T/N35592: R381.1 R382.2 R383.2 TVS44.1(CATHODE)
Drivers IGBT/Red fase T/N35612: R379.2 R382.1 U104.1(+)
Drivers IGBT/Red fase T/N35696: R384.1 U104.3(-)
N08032: JX2.11 R2.1 U1.3(/EF)
N08147: JX2.10 R7.2
N09545: JX1.11 R325.1 R326.1 U95.4(Out)
N09557: JX1.13 R331.1 R332.1 U96.4(Out)
N09575: JX1.17 R337.1 R338.1 U97.4(Out)
N09579: JX1.19 R343.1 R344.1 U98.4(Out)
N09599: JX1.23 ; also on sheet 38
N09603: JX1.25 ; also on sheet 38
N09623: JX1.29 R361.1 R364.1 U101.4(Out)
N09627: JX1.31 R367.1 R368.1 U102.4(Out)
N09647: JX1.35 R373.1 R374.1 U103.4(Out)
N09651: JX1.37 R379.1 R380.1 U104.4(Out)
N09671: JX1.41 R385.1 R386.1 U105.4(Out)
N09675: JX1.43 R391.1 R392.1 U106.4(Out)
N09695: JX1.47 ; also on sheet 37
N09699: JX1.49 ; also on sheet 37
N51075: LED2.2(ANODE) R15.1
N51081: LED3.2(ANODE) R16.1
N51083: LED1.2(ANODE) R14.1

Not connected (* = marked no-connect by the designer): C41 1 2; C42 1 2; C45 1 2; C46 1 2; C49 1 2; C50 1 2; C53 1 2; C54 1 2; D7 1(CATHODE) 2(ANODE); D8 1(CATHODE) 2(ANODE); D9 1(CATHODE) 2(ANODE); D10 1(CATHODE) 2(ANODE); D11 1(CATHODE) 2(ANODE); D12 1(CATHODE) 2(ANODE); D13 1(CATHODE) 2(ANODE); D14 1(CATHODE) 2(ANODE); JX1 1* 2* 3* 4* 5* 6* 7* 8* 9* 10* 12 14 53 63 67 68 69 74 75 76 81 83 87* 88* 89* 90* 91* 92* 93* 94* 97* 98* 99* 100*; JX2 1* 2* 3* 4* 5* 6* 7* 8* 9* 13* 14* 76 93* 94* 95* 96* 97* 99* 100*; R33 1; R34 1; R35 1; R36 1; R37 1; R38 1; R39 1; R40 1; R41 1; R42 1; R43 1; R44 1; R45 1; R46 1; R47 1; R48 1; R49 1; R50 1; R51 1; R52 1; R53 1; R54 1; R55 1; R56 1; R57 1; R58 1; R59 1 2; R60 1; R61 1 2; R62 1 2; R63 1 2; R64 1; R65 1; R66 1; R67 1 2; R68 1; R69 1 2; R70 1 2; R71 1 2; R72 1; R73 1; R74 1; R75 1 2; R76 1; R77 1 2; R78 1 2; R79 1 2; R80 1; R81 1; R82 1; R83 1 2; R84 1; R85 1 2; R86 1 2; R87 1 2; R88 1; R89 1; TVS4 1(CATHODE); TVS5 1(CATHODE); TVS6 1(CATHODE); TVS7 1(CATHODE); TVS8 1(CATHODE); TVS9 1(CATHODE); TVS10 1(CATHODE); TVS11 1(CATHODE); TVS12 1(CATHODE); TVS13 1(CATHODE); TVS14 1(CATHODE); TVS15 1(CATHODE); TVS16 1(CATHODE); TVS17 1(CATHODE); TVS18 1(CATHODE); TVS19 1(CATHODE); TVS20 1(CATHODE); TVS21 1(CATHODE); TVS22 1(CATHODE); TVS23 1(CATHODE); TVS24 1(CATHODE); TVS25 1(CATHODE); TVS26 1(CATHODE) 2(ANODE); TVS27 1(CATHODE) 2(ANODE); TVS28 1(CATHODE) 2(ANODE); TVS29 1(CATHODE) 2(ANODE); TVS30 1(CATHODE) 2(ANODE); TVS31 1(CATHODE) 2(ANODE); TVS32 1(CATHODE) 2(ANODE); TVS33 1(CATHODE) 2(ANODE); U3 3(/EF)* 5(DELAY)*; U10 4(P0) 5(P1) 6(P2) 7(P3) 9(P4) 10(P5) 11(P6) 12(P7) 13(/INT); U11 1(I1) 2(I2) 3(I3) 4(I4) 5(I5) 6(I6) 7(I7) 8(I8) 13(O8) 14(O7) 15(O6) 16(O5) 17(O4) 18(O3) 19(O2) 20(O1); U12 4(P0) 5(P1) 6(P2) 7(P3) 9(P4) 10(P5) 11(P6) 12(P7) 13(/INT); U13 1(I1) 2(I2) 3(I3) 4(I4) 5(I5) 6(I6) 7(I7) 8(I8) 13(O8) 14(O7) 15(O6) 16(O5) 17(O4) 18(O3) 19(O2) 20(O1); U14 4(P0) 6(P2) 7(P3) 9(P4) 10(P5) 11(P6) 12(P7) 13(/INT); U15 1(I1) 2(I2) 3(I3) 4(I4) 5(I5) 6(I6) 7(I7) 8(I8) 13(O8) 14(O7) 15(O6) 16(O5) 17(O4) 18(O3) 19(O2) 20(O1); U16 1(A) 3(K) 5(Vo); U17 1(A) 3(K) 5(Vo); U18 1(A) 3(K) 5(Vo); U19 1(A) 3(K) 5(Vo); U20 1(A) 3(K) 5(Vo); U21 1(A) 3(K) 5(Vo); U22 1(A) 3(K) 5(Vo); U23 1(A) 3(K) 5(Vo); U24 4(P0) 5(P1) 6(P2) 7(P3) 9(P4) 10(P5) 11(P6) 12(P7); X19 5*; X20 5*; X21 5*; X22 5*; X23 5*; X24 5*; X25 5*

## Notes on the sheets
sheet 25
- NM for +3V3D test without MicroZed
sheet 27
- I2C SLAVE
  ADDRESS: 72h
sheet 28
- I2C SLAVE
  ADDRESS: 70h
sheet 29
- I2C SLAVE
  ADDRESS: 70h
sheet 30
- I2C SLAVE
  ADDRESS: 71h
